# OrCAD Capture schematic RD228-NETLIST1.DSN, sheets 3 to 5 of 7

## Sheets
3 5: size A3
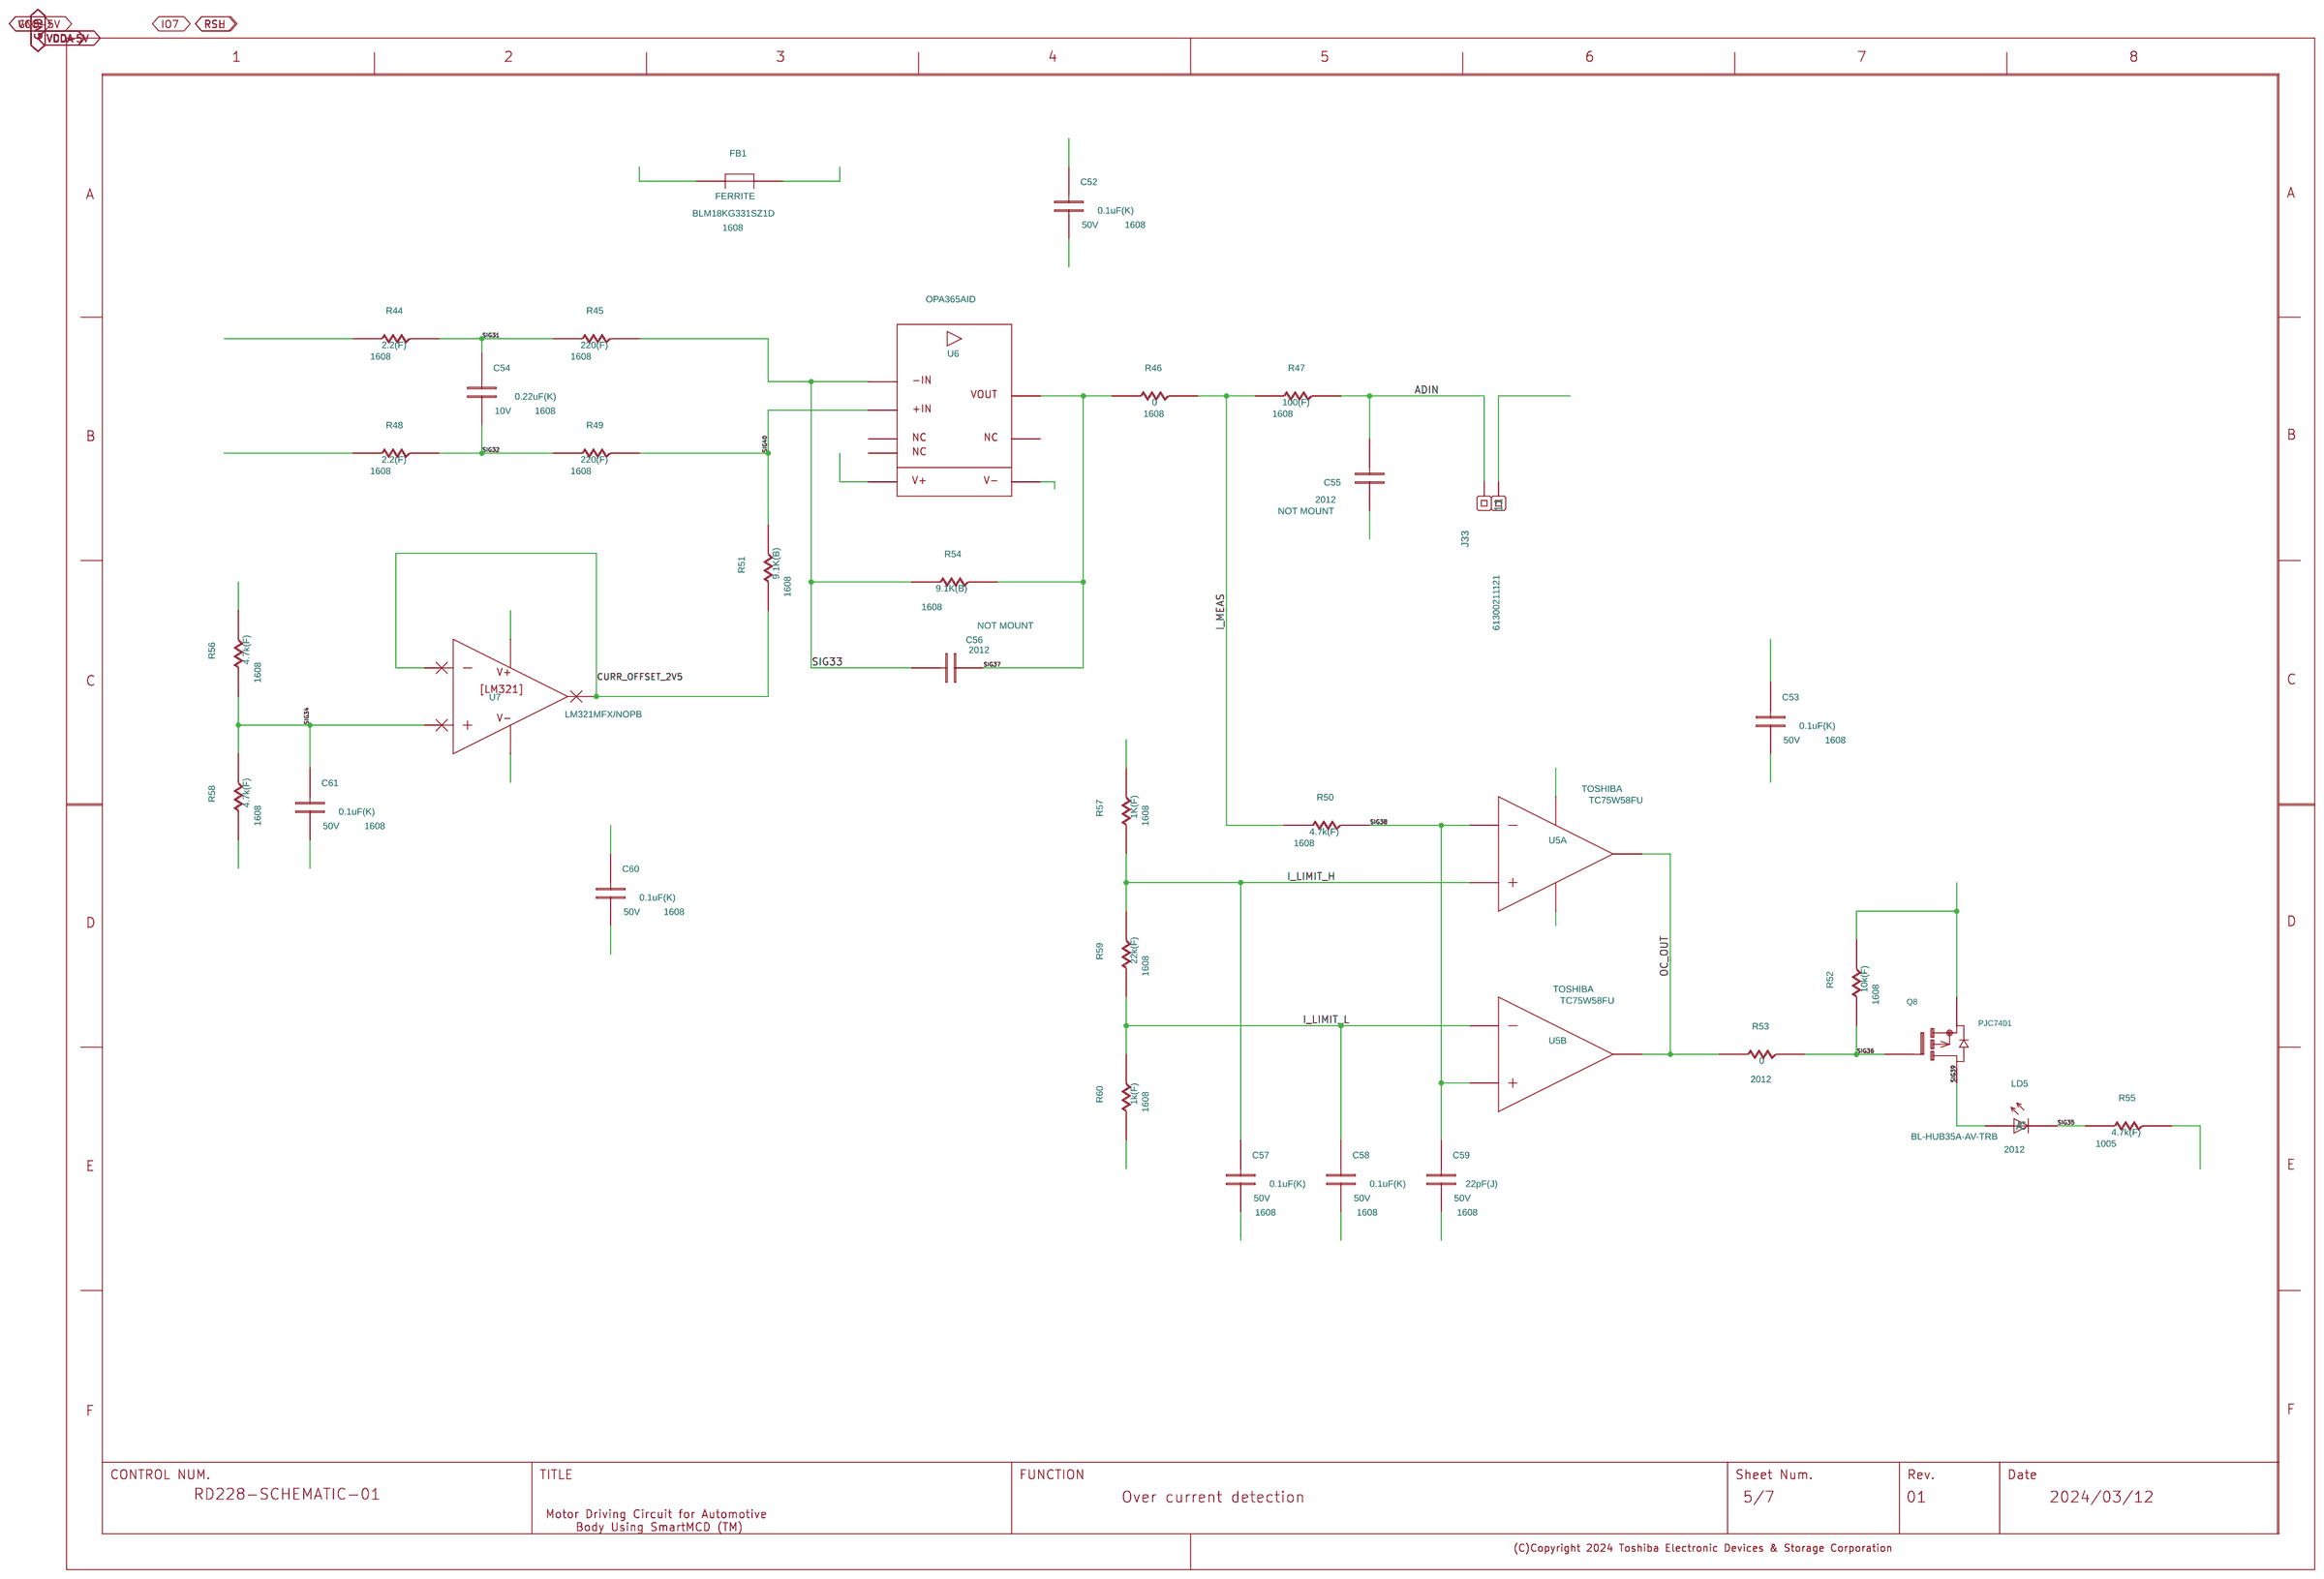
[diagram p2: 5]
4 4: size A3
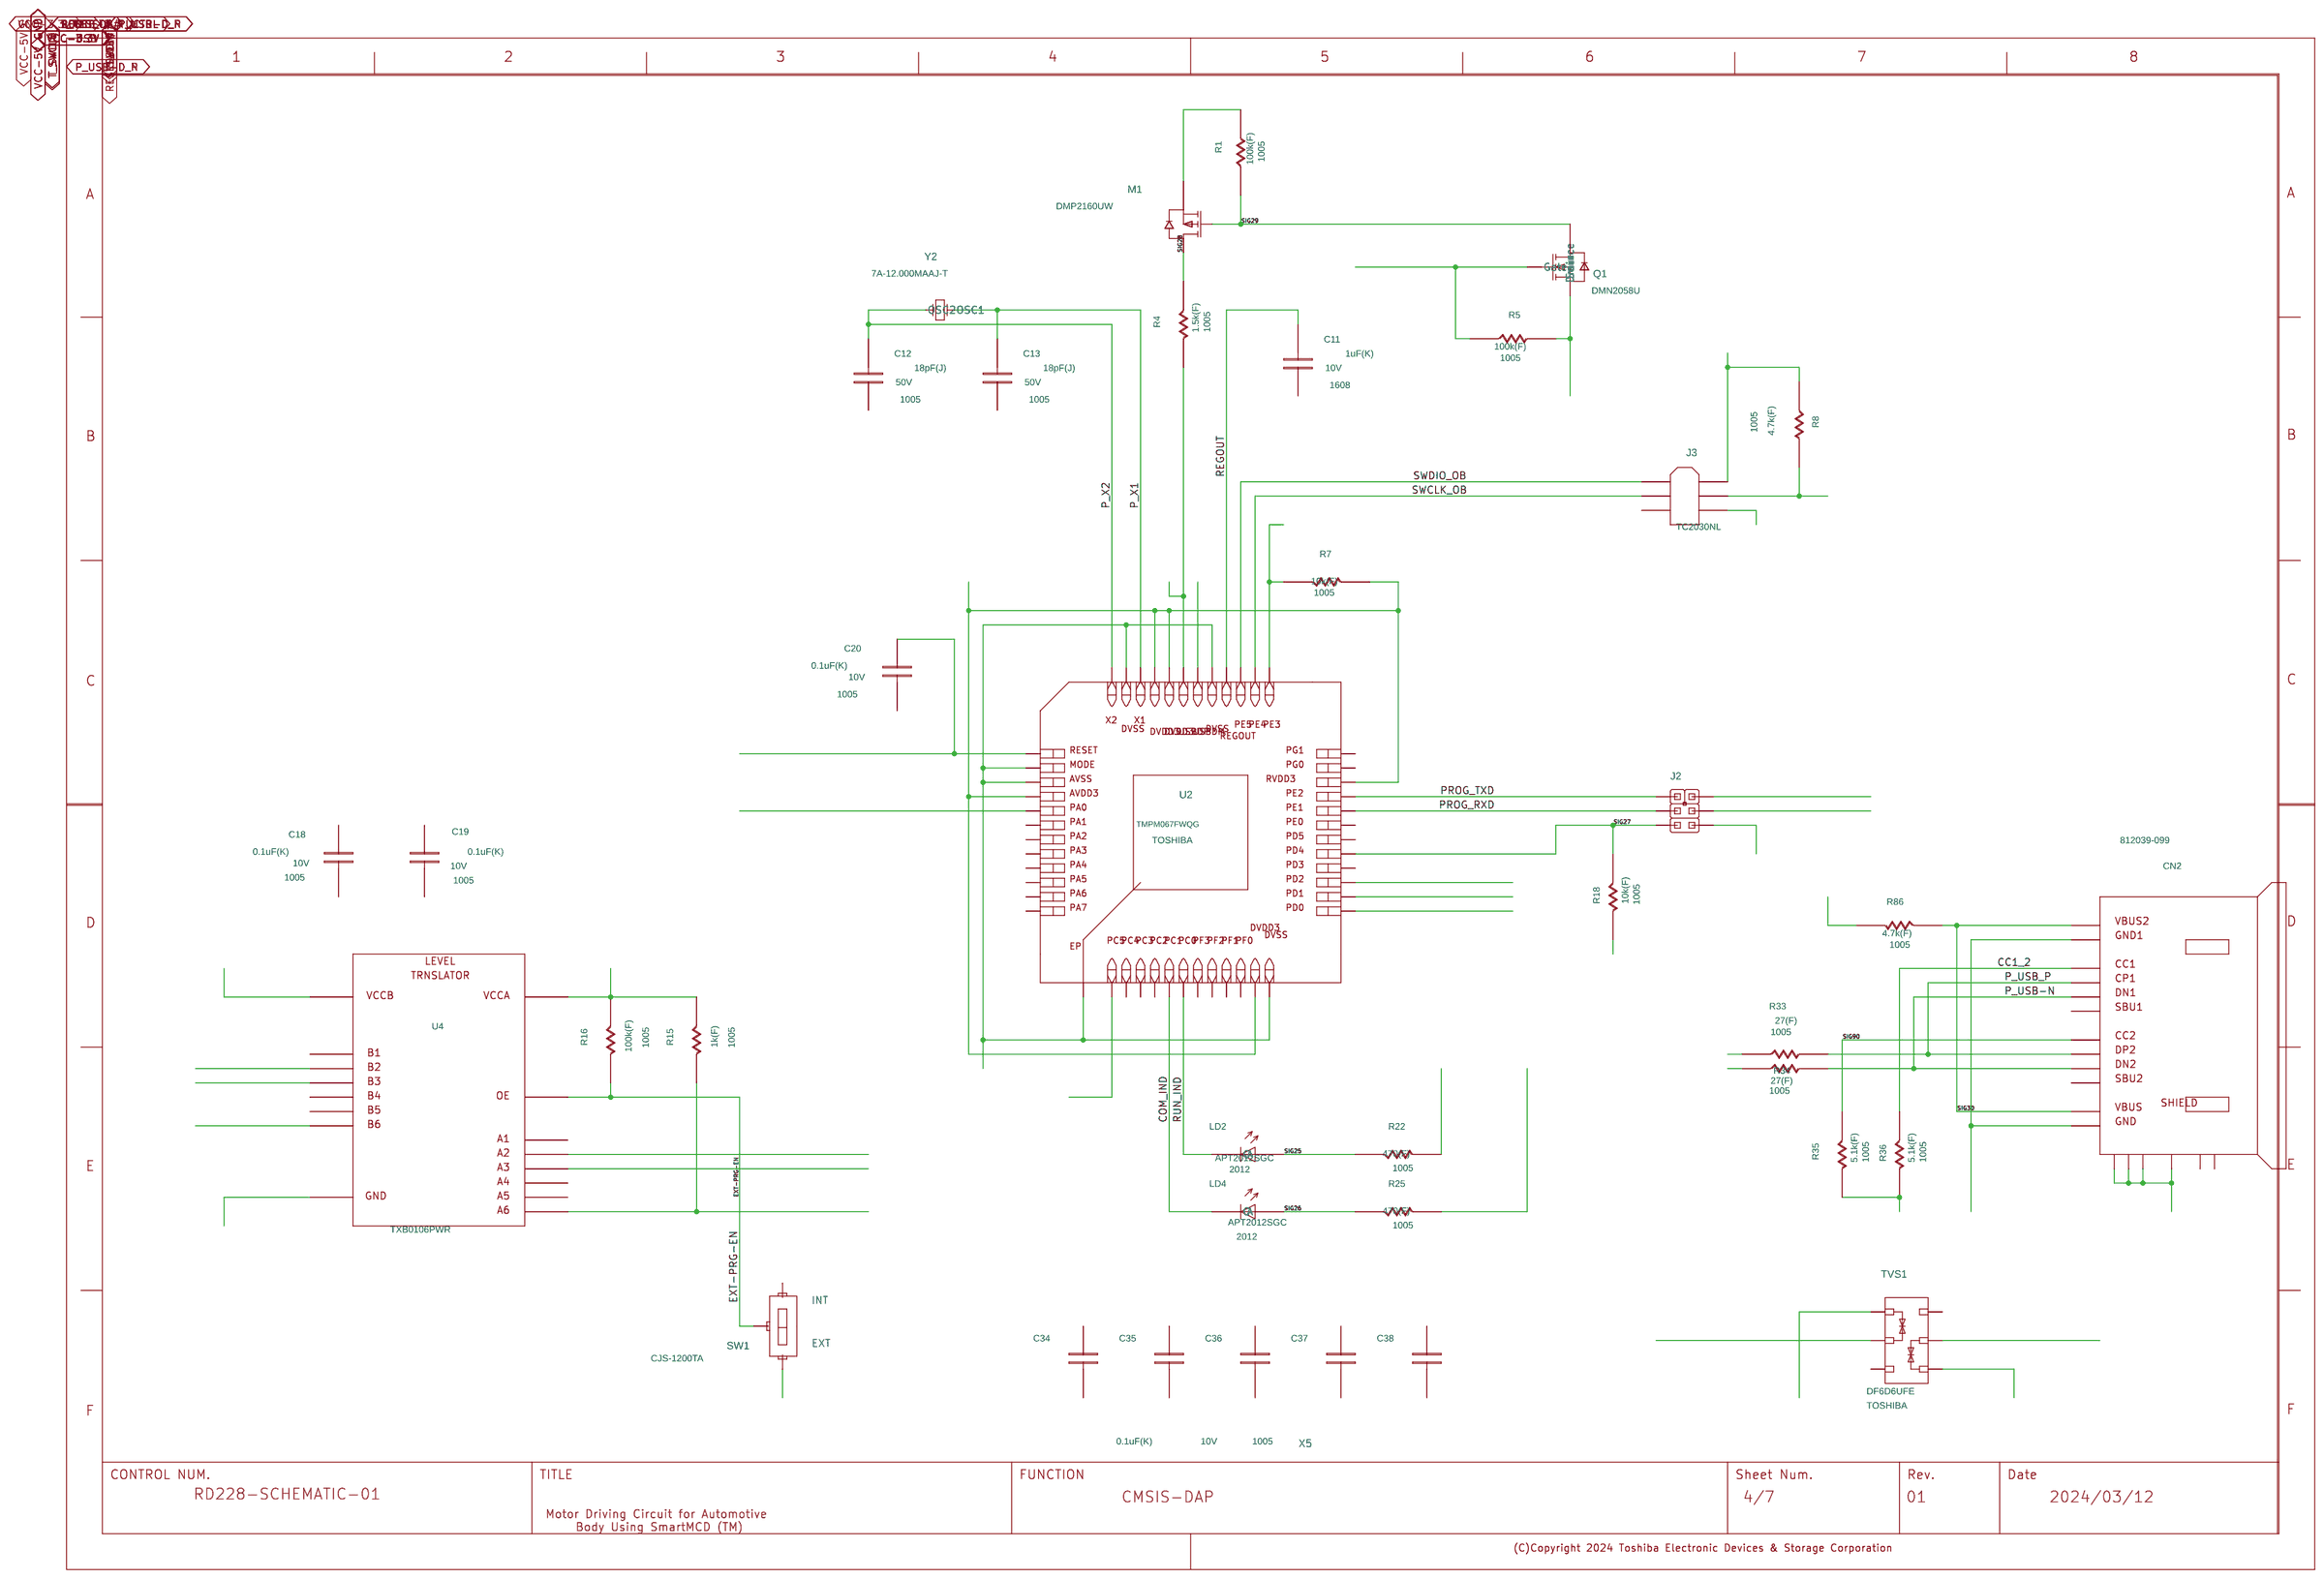
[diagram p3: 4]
5 3: size A3
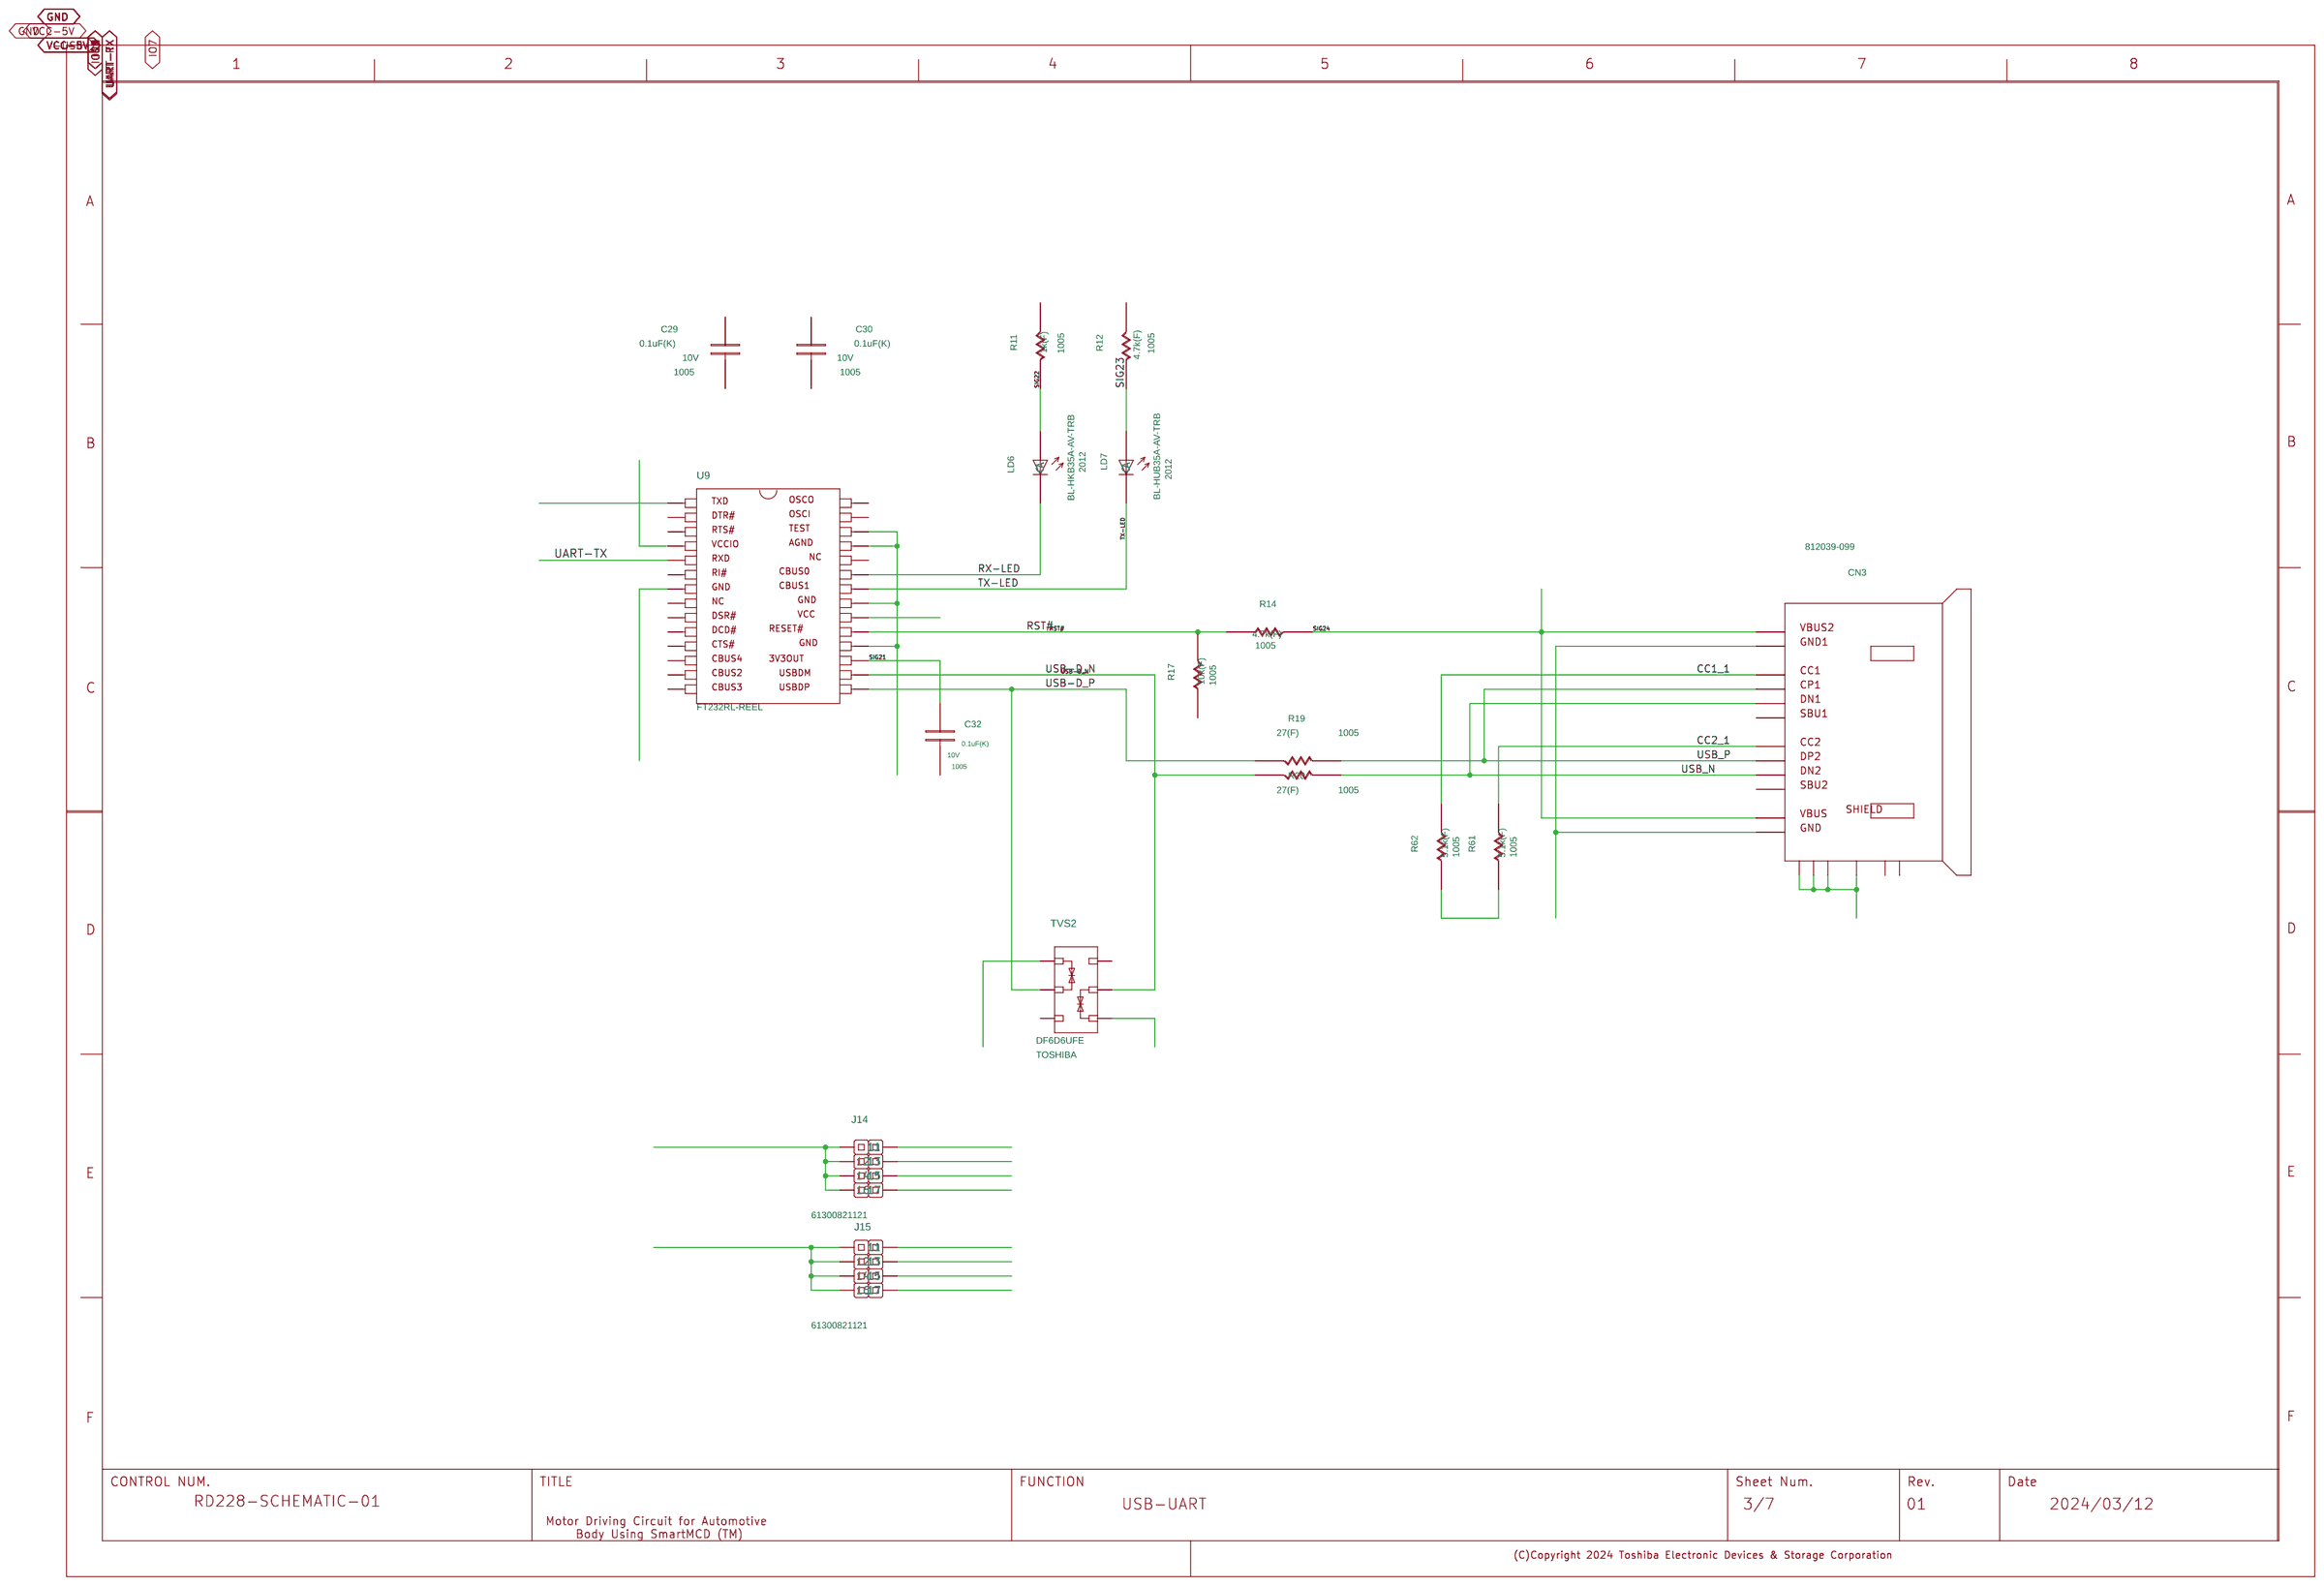
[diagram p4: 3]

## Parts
sheet 3
C29  C
C30  C
C32  C
CN3  USB-C
J14  HM 2x4
J15  HM 2x4
LD6  LED
LD7  LED
R11  R
R12  R
R14  R
R17  R
R19  R
R20  R
R61  R
R62  R
TVS2  NA
U9  FT232RL  [SSOP-28-NoOverlay]
U?#4  WAKU_DEF100
sheet 4
C11  0.1ƒÊF  [CAPC1005X55N-0402-NoOverlay]
C12  0.1ƒÊF  [CAPC1005X55N-0402-NoOverlay]
C13  0.1ƒÊF  [CAPC1005X55N-0402-NoOverlay]
C18  0.1ƒÊF  [CAPC1005X55N-0402-NoOverlay]
C19  0.1ƒÊF  [CAPC1005X55N-0402-NoOverlay]
C20  0.1ƒÊF  [CAPC1005X55N-0402-NoOverlay]
C34  0.1ƒÊF  [CAPC1005X55N-0402-NoOverlay]
C35  0.1ƒÊF  [CAPC1005X55N-0402-NoOverlay]
C36  0.1ƒÊF  [CAPC1005X55N-0402-NoOverlay]
C37  0.1ƒÊF  [CAPC1005X55N-0402-NoOverlay]
C38  0.1ƒÊF  [CAPC1005X55N-0402-NoOverlay]
CN2  USB-C
J2  M2X3
J3  CON-000241-01
LD2  LED
LD4  LED
M1  NA
Q1  MOSFET_N_CHQ1A
R1  R
R4  R
R5  R
R7  R
R8  R
R15  R
R16  R
R18  R
R22  R
R25  R
R33  R
R34  R
R35  R
R36  R
R86  R
SW1  NA
TVS1  NA
U2  NA
U4  TXB0106
U?#3  WAKU_DEF100
Y2  12MHz
sheet 5
C52  0.10ƒÊF  [CAPC1608X55N-0603-NoOverlay]
C53  0.10ƒÊF  [CAPC1608X55N-0603-NoOverlay]
C54  0.22ƒÊF  [CAPC1608X55N-0603-NoOverlay]
C55  NF  [CAPC2013X100N-0805-NoOverlay]
C56  NF  [CAPC2013X100N-0805-NoOverlay]
C57  0.10ƒÊF  [CAPC1608X55N-0603-NoOverlay]
C58  0.10ƒÊF  [CAPC1608X55N-0603-NoOverlay]
C59  22pF  [CAPC1608X55N-0603-NoOverlay]
C60  0.10ƒÊF  [CAPC1608X55N-0603-NoOverlay]
C61  0.10ƒÊF  [CAPC1608X55N-0603-NoOverlay]
FB1  FERRITE  [INDC1608X95N-0603-NOOVERLAY]
J33  M1X2
LD5  FLT1  [DIOREDC2013X120N-0805-NoOverlay]
Q8  NA  [SOT65P210X100-3N-NoOverlay]
R44  2.2R  [RESC1508X55N-0603-NOOVERLAY]
R45  220  [RESC1508X55N-0603-NOOVERLAY]
R46  0R  [RESC1508X55N-0603-NOOVERLAY]
R47  100  [RESC1508X55N-0603-NOOVERLAY]
R48  2.2R  [RESC1508X55N-0603-NOOVERLAY]
R49  220  [RESC1508X55N-0603-NOOVERLAY]
R50  4.7k  [RESC1508X55N-0603-NOOVERLAY]
R51  9.1k  [RESC1508X55N-0603-NOOVERLAY]
R52  10k  [RESC1508X55N-0603-NOOVERLAY]
R53  0.0  [RESC2013X38N-0805-NOOVERLAY]
R54  9.1k  [RESC1508X55N-0603-NOOVERLAY]
R55  4.7k  [RESC1005X40N-0402-NOOVERLAY]
R56  4.7k  [RESC1508X55N-0603-NOOVERLAY]
R57  1k  [RESC1508X55N-0603-NOOVERLAY]
R58  4.7k  [RESC1508X55N-0603-NOOVERLAY]
R59  22k  [RESC1508X55N-0603-NOOVERLAY]
R60  1k  [RESC1508X55N-0603-NOOVERLAY]
U5  NA  [SOP65P400X110-8L30N-TSSOP-8-NoOverlay]  (sections A,B)
U6  NA  [SOIC8P127_490X600X175L83X41N-SOIC8_-_NoOverlay]
U7  NA  [SOT95P280X145-5L30N-SOT23-5-NoOverlay]
U?#2  WAKU_DEF100

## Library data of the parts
C29 C30 C32 = C: COMPONENTTYPE: 4; SAVECOUNT: 0; SIZECODESMD: 1005; VAL1: 0.1uF(K); VAL2: 10V
CN2 CN3 = USB-C: COMP: USB_TYPE_C_CN2; COMPONENTTYPE: 4; VAL3: 812039-099
J14 = HM_2X4_J14: COMPONENTTYPE: 4; LAYOUTNAME: Z-7dc569f5-73f0-43d2-99fa-c8247dcaffbd.cmp50; VAL3: 61300821121
J15 = HM_2X4_J14: COMPONENTTYPE: 4; LAYOUTNAME: Z-7dc569f5-73f0-43d2-99fa-c8247dcaffbd.cmp54; VAL3: 61300821121
LD6 = LED: COMPONENTTYPE: 4; LAYOUTNAME: Z-7dc569f5-73f0-43d2-99fa-c8247dcaffbd.cmp70; SIZECODESMD: 2012; UPDATEDATE: 06/10/13; UPDATETIME: 13:54:07; UPDATEUSER: fukuda-y; VAL1: YELLOW; VAL3: BL-HKB35A-AV-TRB
LD7 = LED: COMPONENTTYPE: 4; LAYOUTNAME: Z-7dc569f5-73f0-43d2-99fa-c8247dcaffbd.cmp71; SIZECODESMD: 2012; UPDATEDATE: 06/10/13; UPDATETIME: 13:54:07; UPDATEUSER: fukuda-y; VAL1: RED; VAL3: BL-HUB35A-AV-TRB
R11 R15 = R: COMPONENTTYPE: 4; SAVECOUNT: 0; SIZECODESMD: 1005; VAL1: 1k(F); VAL2: 63mW
R8 R12 R86 = R: COMPONENTTYPE: 4; SAVECOUNT: 0; SIZECODESMD: 1005; VAL1: 4.7k(F); VAL2: 63mW
R14 = R: COMPONENTTYPE: 4; LAYOUTNAME: Z-7dc569f5-73f0-43d2-99fa-c8247dcaffbd.cmp79; SAVECOUNT: 0; SIZECODESMD: 1005; VAL1: 4.7k(F); VAL2: 63mW
R7 R17 R18 = R: COMPONENTTYPE: 4; SAVECOUNT: 0; SIZECODESMD: 1005; VAL1: 10k(F); VAL2: 63mW
R19 R20 = R: COMPONENTTYPE: 4; SAVECOUNT: 0; SIZECODESMD: 1005; VAL1: 27(F); VAL2: 63mW
R35 R36 R61 R62 = R: COMPONENTTYPE: 4; SAVECOUNT: 0; SIZECODESMD: 1005; VAL1: 5.1k(F); VAL2: 63mW
TVS2 = DF6D6UFE_L3F_TVS1: COMPONENTTYPE: 4; LAYOUTNAME: Z-7dc569f5-73f0-43d2-99fa-c8247dcaffbd.cmp105; USERCOMPTEXT3: TOSHIBA; VAL3: DF6D6UFE
U9 = FT232RL_U9: COMPONENTNAME: FT232RL_U9_FT232RL_U9; COMPONENTTYPE: 4; INSTANCENAME: INS4949; LAYOUTNAME: Z-7dc569f5-73f0-43d2-99fa-c8247dcaffbd.cmp9; UPDATEDATE: 2024/2/16; UPDATETIME: 16:56:39; VAL3: FT232RL-REEL
U?#4 = WAKU_DEF100: AUTHOR: w20165dm; COMPONENTTYPE: 2; DATE: 2024/03/12; DRAWINGNUMBER: RD228-SCHEMATIC-01; FUNCTION: USB-UART; LAYOUTNAME: Z-7dc569f5-73f0-43d2-99fa-c8247dcaffbd.cmp39; REVISION: 01; SAVEAREA0: 185750,-43960,448537,75779; SAVECOUNT: 9; SHEETNUMBER: 3/7; SHTSAVECOUNT: 40; TIME: 13:11:45; TITLE: Motor Driving Circuit for Automotive / Body Using SmartMCD (TM); UPDATEDATE: 2024/03/26; UPDATETIME: 12:23:37
C11 = C: ASSEMBLY: SMD; AUTHOR: t5459927; BARCODE: 2911010025755; CATEGORY: Capacitors; COMP: Capacitor_Ceramic_C19; COMPONENTTYPE: 4; DATASHEET URL: http://ds.yuden.co.jp/TYCOMPAS/ut/detail.do?productNo; DATE: 2024/2/16; FAMILY: CERAMIC CAPACITOR; INSTANCENAME: INS3745; LAYOUTNAME: Z-3a01232a-ff64-4668-b530-789526b9f0c3.cmp194; MANUFACTURER: Taiyo Yuden; MANUFACTURER PART NUMBER: LMK105BJ104KV-F; NUMBER DEVICES IN PACKAGE: 1; PACKAGE CASE: 0402 (1005 Metric); PART TYPE: Capacitors; PIN NAMES ROTATE: True; PIN NAMES VISIBLE: False; PIN NUMBERS VISIBLE: False; RECOMMENDED RATING: Platinum; SAVECOUNT: 0; SIZECODESMD: 1608; TEMPERATURE COEFFICIENT: X5R; TIME: 16:56:44; TOLERANCE: }10%; UPDATEDATE: 2024/2/16; UPDATETIME: 16:56:44; UPDATEUSER: t5459927; VAL1: 1uF(K); VAL2: 10V; VOLTAGE RATED: 10V
C12 = C: ASSEMBLY: SMD; AUTHOR: t5459927; BARCODE: 2911010025755; CATEGORY: Capacitors; COMP: Capacitor_Ceramic_C19; COMPONENTTYPE: 4; DATASHEET URL: http://ds.yuden.co.jp/TYCOMPAS/ut/detail.do?productNo; DATE: 2024/2/16; FAMILY: CERAMIC CAPACITOR; INSTANCENAME: INS3745; LAYOUTNAME: Z-3a01232a-ff64-4668-b530-789526b9f0c3.cmp185; MANUFACTURER: Taiyo Yuden; MANUFACTURER PART NUMBER: LMK105BJ104KV-F; NUMBER DEVICES IN PACKAGE: 1; PACKAGE CASE: 0402 (1005 Metric); PART TYPE: Capacitors; PIN NAMES ROTATE: True; PIN NAMES VISIBLE: False; PIN NUMBERS VISIBLE: False; RECOMMENDED RATING: Platinum; SAVECOUNT: 0; SIZECODESMD: 1005; TEMPERATURE COEFFICIENT: X5R; TIME: 16:56:44; TOLERANCE: }10%; UPDATEDATE: 2024/2/16; UPDATETIME: 16:56:44; UPDATEUSER: t5459927; VAL1: 18pF(J); VAL2: 50V; VOLTAGE RATED: 10V
C13 = C: ASSEMBLY: SMD; AUTHOR: t5459927; BARCODE: 2911010025755; CATEGORY: Capacitors; COMP: Capacitor_Ceramic_C19; COMPONENTTYPE: 4; DATASHEET URL: http://ds.yuden.co.jp/TYCOMPAS/ut/detail.do?productNo; DATE: 2024/2/16; FAMILY: CERAMIC CAPACITOR; INSTANCENAME: INS3745; LAYOUTNAME: Z-3a01232a-ff64-4668-b530-789526b9f0c3.cmp189; MANUFACTURER: Taiyo Yuden; MANUFACTURER PART NUMBER: LMK105BJ104KV-F; NUMBER DEVICES IN PACKAGE: 1; PACKAGE CASE: 0402 (1005 Metric); PART TYPE: Capacitors; PIN NAMES ROTATE: True; PIN NAMES VISIBLE: False; PIN NUMBERS VISIBLE: False; RECOMMENDED RATING: Platinum; SAVECOUNT: 0; SIZECODESMD: 1005; TEMPERATURE COEFFICIENT: X5R; TIME: 16:56:44; TOLERANCE: }10%; UPDATEDATE: 2024/2/16; UPDATETIME: 16:56:44; UPDATEUSER: t5459927; VAL1: 18pF(J); VAL2: 50V; VOLTAGE RATED: 10V
C18 = C: ASSEMBLY: SMD; AUTHOR: t5459927; BARCODE: 2911010025755; CATEGORY: Capacitors; COMP: Capacitor_Ceramic_C18; COMPONENTTYPE: 4; DATASHEET URL: http://ds.yuden.co.jp/TYCOMPAS/ut/detail.do?productNo; DATE: 2024/2/16; FAMILY: CERAMIC CAPACITOR; INSTANCENAME: INS3745; MANUFACTURER: Taiyo Yuden; MANUFACTURER PART NUMBER: LMK105BJ104KV-F; NUMBER DEVICES IN PACKAGE: 1; PACKAGE CASE: 0402 (1005 Metric); PART TYPE: Capacitors; PIN NAMES ROTATE: True; PIN NAMES VISIBLE: False; PIN NUMBERS VISIBLE: False; RECOMMENDED RATING: Platinum; SAVECOUNT: 0; SIZECODESMD: 1005; TEMPERATURE COEFFICIENT: X5R; TIME: 16:56:44; TOLERANCE: }10%; UPDATEDATE: 2024/2/16; UPDATETIME: 16:56:44; UPDATEUSER: t5459927; VAL1: 0.1uF(K); VAL2: 10V; VOLTAGE RATED: 10V
C19 C34-C38 = C: ASSEMBLY: SMD; AUTHOR: t5459927; BARCODE: 2911010025755; CATEGORY: Capacitors; COMP: Capacitor_Ceramic_C19; COMPONENTTYPE: 4; DATASHEET URL: http://ds.yuden.co.jp/TYCOMPAS/ut/detail.do?productNo; DATE: 2024/2/16; FAMILY: CERAMIC CAPACITOR; INSTANCENAME: INS3745; MANUFACTURER: Taiyo Yuden; MANUFACTURER PART NUMBER: LMK105BJ104KV-F; NUMBER DEVICES IN PACKAGE: 1; PACKAGE CASE: 0402 (1005 Metric); PART TYPE: Capacitors; PIN NAMES ROTATE: True; PIN NAMES VISIBLE: False; PIN NUMBERS VISIBLE: False; RECOMMENDED RATING: Platinum; SAVECOUNT: 0; SIZECODESMD: 1005; TEMPERATURE COEFFICIENT: X5R; TIME: 16:56:44; TOLERANCE: }10%; UPDATEDATE: 2024/2/16; UPDATETIME: 16:56:44; UPDATEUSER: t5459927; VAL1: 0.1uF(K); VAL2: 10V; VOLTAGE RATED: 10V
C20 = C: ASSEMBLY: SMD; AUTHOR: t5459927; BARCODE: 2911010025755; CATEGORY: Capacitors; COMP: Capacitor_Ceramic_C20; COMPONENTTYPE: 4; DATASHEET URL: http://ds.yuden.co.jp/TYCOMPAS/ut/detail.do?productNo; DATE: 2024/2/16; FAMILY: CERAMIC CAPACITOR; INSTANCENAME: INS3745; MANUFACTURER: Taiyo Yuden; MANUFACTURER PART NUMBER: LMK105BJ104KV-F; NUMBER DEVICES IN PACKAGE: 1; PACKAGE CASE: 0402 (1005 Metric); PART TYPE: Capacitors; PIN NAMES ROTATE: True; PIN NAMES VISIBLE: False; PIN NUMBERS VISIBLE: False; RECOMMENDED RATING: Platinum; SAVECOUNT: 0; SIZECODESMD: 1005; TEMPERATURE COEFFICIENT: X5R; TIME: 16:56:44; TOLERANCE: }10%; UPDATEDATE: 2024/2/16; UPDATETIME: 16:56:44; UPDATEUSER: t5459927; VAL1: 0.1uF(K); VAL2: 10V; VOLTAGE RATED: 10V
J2 = JUMPER3_ALT_J2: COMPONENTTYPE: 4; LAYOUTNAME: Z-3a01232a-ff64-4668-b530-789526b9f0c3.cmp174; VAL3: 892-70-006-10-001101
J3 = CON_000241_01_J3: COMPONENTTYPE: 4; LAYOUTNAME: Z-3a01232a-ff64-4668-b530-789526b9f0c3.cmp232; VAL3: TC2030NL
LD2 = LED: COMP: APT2012SGC; COMPONENTTYPE: 4; LAYOUTNAME: Z-3a01232a-ff64-4668-b530-789526b9f0c3.cmp168; SIZECODESMD: 2012; UPDATEDATE: 06/10/13; UPDATETIME: 13:54:07; UPDATEUSER: fukuda-y; VAL1: GREEN; VAL3: APT2012SGC
LD4 = LED: COMP: APT2012SGC; COMPONENTTYPE: 4; LAYOUTNAME: Z-3a01232a-ff64-4668-b530-789526b9f0c3.cmp169; SIZECODESMD: 2012; UPDATEDATE: 06/10/13; UPDATETIME: 13:54:07; UPDATEUSER: fukuda-y; VAL1: GREEN; VAL3: APT2012SGC
M1 = MOSFET_P_CH_M1: COMPONENTTYPE: 4; LAYOUTNAME: Z-3a01232a-ff64-4668-b530-789526b9f0c3.cmp191; VAL3: DMP2160UW
Q1 = MOSFET_N_CHQ1A: COMP: Q; COMPONENTKIND: 0; COMPONENTTYPE: 4; LAYOUTNAME: Z-3a01232a-ff64-4668-b530-789526b9f0c3.cmp228; VAL3: DMN2058U
R1 = R: COMPONENTTYPE: 4; LAYOUTNAME: Z-3a01232a-ff64-4668-b530-789526b9f0c3.cmp195; SAVECOUNT: 0; SIZECODESMD: 1005; VAL1: 100k(F); VAL2: 100mW
R4 = R: COMPONENTTYPE: 4; SAVECOUNT: 0; SIZECODESMD: 1005; VAL1: 1.5k(F); VAL2: 100mW
R5 = R: COMPONENTTYPE: 4; LAYOUTNAME: Z-3a01232a-ff64-4668-b530-789526b9f0c3.cmp199; SAVECOUNT: 0; SIZECODESMD: 1005; VAL1: 100k(F); VAL2: 100mW
R16 = R: COMPONENTTYPE: 4; SAVECOUNT: 0; SIZECODESMD: 1005; VAL1: 100k(F); VAL2: 63mW
R22 R25 = R: COMPONENTTYPE: 4; SAVECOUNT: 0; SIZECODESMD: 1005; VAL1: 470(F); VAL2: 63mW
R33 = R: COMPONENTTYPE: 4; LAYOUTNAME: Z-3a01232a-ff64-4668-b530-789526b9f0c3.cmp215; SAVECOUNT: 0; SIZECODESMD: 1005; VAL1: 27(F); VAL2: 63mW
R34 = R: COMPONENTTYPE: 4; LAYOUTNAME: Z-3a01232a-ff64-4668-b530-789526b9f0c3.cmp216; SAVECOUNT: 0; SIZECODESMD: 1005; VAL1: 27(F); VAL2: 63mW
SW1 = CAS_120TA_SW1: COMPONENTTYPE: 4; LAYOUTNAME: Z-3a01232a-ff64-4668-b530-789526b9f0c3.cmp84; VAL3: CJS-1200TA
TVS1 = DF6D6UFE_L3F_TVS1: COMPONENTTYPE: 4; LAYOUTNAME: Z-3a01232a-ff64-4668-b530-789526b9f0c3.cmp222; USERCOMPTEXT3: TOSHIBA; VAL3: DF6D6UFE
U2 = TMPM067FWQG_U2: COMPONENTTYPE: 4; LAYOUTNAME: Z-3a01232a-ff64-4668-b530-789526b9f0c3.cmp229; USERCOMPTEXT3: TOSHIBA; VAL3: TMPM067FWQG
U4 = TXB0106: COMP: U; COMPONENTTYPE: 4; LAYOUTNAME: Z-3a01232a-ff64-4668-b530-789526b9f0c3.cmp93; VAL3: TXB0106PWR
U?#3 = WAKU_DEF100: AUTHOR: w20165dm; COMPONENTTYPE: 2; DATE: 2024/03/12; DRAWINGNUMBER: RD228-SCHEMATIC-01; FUNCTION: CMSIS-DAP; LAYOUTNAME: Z-3a01232a-ff64-4668-b530-789526b9f0c3.cmp82; REVISION: 01; SAVEAREA0: 185750,-43960,448537,75779; SAVECOUNT: 9; SHEETNUMBER: 4/7; SHTSAVECOUNT: 62; TIME: 13:11:54; TITLE: Motor Driving Circuit for Automotive / Body Using SmartMCD (TM); UPDATEDATE: 2024/03/18; UPDATETIME: 20:08:52
Y2 = CRYSTAL_Y2: COMPONENTTYPE: 4; LAYOUTNAME: Z-3a01232a-ff64-4668-b530-789526b9f0c3.cmp188; VAL3: 7A-12.000MAAJ-T
C52 = C: ASSEMBLY: SMD; AUTHOR: t5459927; BARCODE: 0100000012857; CATEGORY: Capacitors; COMP: Capacitor_Ceramic_C52; COMPONENTNAME: Capacitor_Ceramic_C52_Capacitor_Ceramic_C52; COMPONENTTYPE: 4; DATASHEET URL: http://www.samsungsem.com/kr/support/product-search/mlcc/CL10B104KB8NNNC.jsp; DATE: 2024/2/16; FAMILY: CERAMIC CAPACITOR; ID: 275; INSTANCENAME: INS4165; ITEM_ID: 1703; LAYOUTNAME: Z-99fa7a59-0340-4c54-926f-366210f15152.cmp12; MANUFACTURER: Samsung Electro-Mechanics America, Inc.; MANUFACTURER PART NUMBER: CL10B104KB8NNNC; NUMBER DEVICES IN PACKAGE: 1; PACKAGE CASE: 0603 (1608 Metric); PART TYPE: Capacitors; PIN NAMES ROTATE: True; PIN NAMES VISIBLE: False; PIN NUMBERS VISIBLE: False; SAVECOUNT: 0; SIZECODESMD: 1608; TEMPERATURE COEFFICIENT: X7R; TIME: 16:56:37; TOLERANCE: }10%; UPDATEDATE: 2024/2/16; UPDATETIME: 16:56:37; UPDATEUSER: t5459927; VAL1: 0.1uF(K); VAL2: 50V; VAL3: CL10B104KB8NNNC; VOLTAGE RATED: 50V
C53 = C: ASSEMBLY: SMD; AUTHOR: t5459927; BARCODE: 0100000012857; CATEGORY: Capacitors; COMP: Capacitor_Ceramic_C53; COMPONENTNAME: Capacitor_Ceramic_C53_Capacitor_Ceramic_C53; COMPONENTTYPE: 4; DATASHEET URL: http://www.samsungsem.com/kr/support/product-search/mlcc/CL10B104KB8NNNC.jsp; DATE: 2024/2/16; FAMILY: CERAMIC CAPACITOR; ID: 275; INSTANCENAME: INS4313; ITEM_ID: 1703; LAYOUTNAME: Z-99fa7a59-0340-4c54-926f-366210f15152.cmp15; MANUFACTURER: Samsung Electro-Mechanics America, Inc.; MANUFACTURER PART NUMBER: CL10B104KB8NNNC; NUMBER DEVICES IN PACKAGE: 1; PACKAGE CASE: 0603 (1608 Metric); PART TYPE: Capacitors; PIN NAMES ROTATE: True; PIN NAMES VISIBLE: False; PIN NUMBERS VISIBLE: False; SAVECOUNT: 0; SIZECODESMD: 1608; TEMPERATURE COEFFICIENT: X7R; TIME: 16:56:55; TOLERANCE: }10%; UPDATEDATE: 2024/2/16; UPDATETIME: 16:56:55; UPDATEUSER: t5459927; VAL1: 0.1uF(K); VAL2: 50V; VAL3: CL10B104KB8NNNC; VOLTAGE RATED: 50V
C54 = C: ASSEMBLY: SMD; AUTHOR: t5459927; BARCODE: 3500000320896; CATEGORY: Capacitors; COMP: Capacitor_Ceramic_C54; COMPONENTNAME: Capacitor_Ceramic_C54_Capacitor_Ceramic_C54; COMPONENTTYPE: 4; DATASHEET URL: http://www.calchipelectronics.com/pdf/gmc_series.pdf; DATE: 2024/2/16; FAMILY: CERAMIC CAPACITOR; ID: 1358; INSTANCENAME: INS4245; ITEM_ID: 29240; LAYOUTNAME: Z-99fa7a59-0340-4c54-926f-366210f15152.cmp33; MANUFACTURER: CAL-CHIP ELECTRONICS, INC.; MANUFACTURER PART NUMBER: GMC10X7R224K10NT; NUMBER DEVICES IN PACKAGE: 1; PACKAGE CASE: 0603 (1608 Metric); PART TYPE: Capacitors; PIN NAMES ROTATE: True; PIN NAMES VISIBLE: False; PIN NUMBERS VISIBLE: False; SAVECOUNT: 0; SIZECODESMD: 1608; TEMPERATURE COEFFICIENT: X7R; TIME: 16:56:54; TOLERANCE: }10%; UPDATEDATE: 2024/2/16; UPDATETIME: 16:56:54; UPDATEUSER: t5459927; VAL1: 0.22uF(K); VAL2: 10V; VAL3: GMC10X7R224K10NT; VOLTAGE RATED: 10V
C55 = C: ASSEMBLY: SMD; AUTHOR: t5459927; BARCODE: 0100000001868; CAPACITANCE: 100n; CATEGORY: Capacitors; COMP: Capacitor_Ceramic_C55; COMPONENTNAME: Capacitor_Ceramic_C55_Capacitor_Ceramic_C55; COMPONENTTYPE: 4; DATE: 2024/2/16; FAMILY: CERAMIC CAPACITOR; ID: 136; INSTANCENAME: INS4255; ITEM_ID: 450; LAYOUTNAME: Z-99fa7a59-0340-4c54-926f-366210f15152.cmp55; MANUFACTURER: Yageo; MANUFACTURER PART NUMBER: CC0805KRX7R9BB104; NOTMOUNT: NOT MOUNT; NUMBER DEVICES IN PACKAGE: 1; PACKAGE CASE: 0805; PART TYPE: Capacitors; PIN NAMES ROTATE: True; PIN NAMES VISIBLE: False; PIN NUMBERS VISIBLE: False; RECOMMENDED RATING: Platinum; SAVECOUNT: 0; TEMPERATURE COEFFICIENT: X7R; TIME: 16:56:44; TOLERANCE: 10%; UPDATEDATE: 2024/2/16; UPDATETIME: 16:56:44; UPDATEUSER: t5459927; VAL3: 2012; VOLTAGE RATED: 50
C56 = C: ASSEMBLY: SMD; AUTHOR: t5459927; BARCODE: 0100000001868; CAPACITANCE: 100n; CATEGORY: Capacitors; COMP: Capacitor_Ceramic_C56; COMPONENTNAME: Capacitor_Ceramic_C56_Capacitor_Ceramic_C56; COMPONENTTYPE: 4; DATE: 2024/2/16; FAMILY: CERAMIC CAPACITOR; ID: 136; INSTANCENAME: INS4265; ITEM_ID: 450; LAYOUTNAME: Z-99fa7a59-0340-4c54-926f-366210f15152.cmp8; MANUFACTURER: Yageo; MANUFACTURER PART NUMBER: CC0805KRX7R9BB104; NOTMOUNT: NOT MOUNT; NUMBER DEVICES IN PACKAGE: 1; PACKAGE CASE: 0805; PART TYPE: Capacitors; PIN NAMES ROTATE: True; PIN NAMES VISIBLE: False; PIN NUMBERS VISIBLE: False; RECOMMENDED RATING: Platinum; SAVECOUNT: 0; TEMPERATURE COEFFICIENT: X7R; TIME: 16:56:58; TOLERANCE: 10%; UPDATEDATE: 2024/2/16; UPDATETIME: 16:56:58; UPDATEUSER: t5459927; VAL3: 2012; VOLTAGE RATED: 50
C57 = C: ASSEMBLY: SMD; AUTHOR: t5459927; BARCODE: 0100000012857; CATEGORY: Capacitors; COMP: Capacitor_Ceramic_C57; COMPONENTNAME: Capacitor_Ceramic_C57_Capacitor_Ceramic_C57; COMPONENTTYPE: 4; DATASHEET URL: http://www.samsungsem.com/kr/support/product-search/mlcc/CL10B104KB8NNNC.jsp; DATE: 2024/2/16; FAMILY: CERAMIC CAPACITOR; ID: 275; INSTANCENAME: INS4343; ITEM_ID: 1703; LAYOUTNAME: Z-99fa7a59-0340-4c54-926f-366210f15152.cmp54; MANUFACTURER: Samsung Electro-Mechanics America, Inc.; MANUFACTURER PART NUMBER: CL10B104KB8NNNC; NUMBER DEVICES IN PACKAGE: 1; PACKAGE CASE: 0603 (1608 Metric); PART TYPE: Capacitors; PIN NAMES ROTATE: True; PIN NAMES VISIBLE: False; PIN NUMBERS VISIBLE: False; SAVECOUNT: 0; SIZECODESMD: 1608; TEMPERATURE COEFFICIENT: X7R; TIME: 16:56:48; TOLERANCE: }10%; UPDATEDATE: 2024/2/16; UPDATETIME: 16:56:48; UPDATEUSER: t5459927; VAL1: 0.1uF(K); VAL2: 50V; VAL3: CL10B104KB8NNNC; VOLTAGE RATED: 50V
C58 = C: ASSEMBLY: SMD; AUTHOR: t5459927; BARCODE: 0100000012857; CATEGORY: Capacitors; COMP: Capacitor_Ceramic_C58; COMPONENTNAME: Capacitor_Ceramic_C58_Capacitor_Ceramic_C58; COMPONENTTYPE: 4; DATASHEET URL: http://www.samsungsem.com/kr/support/product-search/mlcc/CL10B104KB8NNNC.jsp; DATE: 2024/2/16; FAMILY: CERAMIC CAPACITOR; ID: 275; INSTANCENAME: INS4333; ITEM_ID: 1703; LAYOUTNAME: Z-99fa7a59-0340-4c54-926f-366210f15152.cmp6; MANUFACTURER: Samsung Electro-Mechanics America, Inc.; MANUFACTURER PART NUMBER: CL10B104KB8NNNC; NUMBER DEVICES IN PACKAGE: 1; PACKAGE CASE: 0603 (1608 Metric); PART TYPE: Capacitors; PIN NAMES ROTATE: True; PIN NAMES VISIBLE: False; PIN NUMBERS VISIBLE: False; SAVECOUNT: 0; SIZECODESMD: 1608; TEMPERATURE COEFFICIENT: X7R; TIME: 16:56:59; TOLERANCE: }10%; UPDATEDATE: 2024/2/16; UPDATETIME: 16:56:59; UPDATEUSER: t5459927; VAL1: 0.1uF(K); VAL2: 50V; VAL3: CL10B104KB8NNNC; VOLTAGE RATED: 50V
C59 = C: ASSEMBLY: SMD; AUTHOR: t5459927; BARCODE: 0100000013731; CATEGORY: Capacitors; COMP: Capacitor_Ceramic_C59; COMPONENTNAME: Capacitor_Ceramic_C59_Capacitor_Ceramic_C59; COMPONENTTYPE: 4; DATASHEET URL: http://www.yageo.com/documents/recent/UPY-GP_NP0_16V-to-50V_10.pdf; DATE: 2024/2/16; FAMILY: CERAMIC CAPACITOR; ID: 145; INSTANCENAME: INS4323; ITEM_ID: 1791; LAYOUTNAME: Z-99fa7a59-0340-4c54-926f-366210f15152.cmp57; MANUFACTURER: Yageo; MANUFACTURER PART NUMBER: CC0603JRNPO9BN220; NUMBER DEVICES IN PACKAGE: 1; PACKAGE CASE: 0603 (1608 Metric); PART TYPE: Capacitors; PIN NAMES ROTATE: True; PIN NAMES VISIBLE: False; PIN NUMBERS VISIBLE: False; RECOMMENDED RATING: Platinum; SAVECOUNT: 0; SIZECODESMD: 1608; TEMPERATURE COEFFICIENT: C0G, NP0; TIME: 16:56:45; TOLERANCE: }5%; UPDATEDATE: 2024/2/16; UPDATETIME: 16:56:45; UPDATEUSER: t5459927; VAL1: 22pF(J); VAL2: 50V; VAL3: CC0603JRNPO9BN220; VOLTAGE RATED: 50V
C60 = C: ASSEMBLY: SMD; AUTHOR: t5459927; BARCODE: 0100000012857; CATEGORY: Capacitors; COMP: Capacitor_Ceramic_C60; COMPONENTNAME: Capacitor_Ceramic_C60_Capacitor_Ceramic_C60; COMPONENTTYPE: 4; DATASHEET URL: http://www.samsungsem.com/kr/support/product-search/mlcc/CL10B104KB8NNNC.jsp; DATE: 2024/2/16; FAMILY: CERAMIC CAPACITOR; ID: 275; INSTANCENAME: INS4607; ITEM_ID: 1703; LAYOUTNAME: Z-99fa7a59-0340-4c54-926f-366210f15152.cmp31; MANUFACTURER: Samsung Electro-Mechanics America, Inc.; MANUFACTURER PART NUMBER: CL10B104KB8NNNC; NUMBER DEVICES IN PACKAGE: 1; PACKAGE CASE: 0603 (1608 Metric); PART TYPE: Capacitors; PIN NAMES ROTATE: True; PIN NAMES VISIBLE: False; PIN NUMBERS VISIBLE: False; SAVECOUNT: 0; SIZECODESMD: 1608; TEMPERATURE COEFFICIENT: X7R; TIME: 16:56:37; TOLERANCE: }10%; UPDATEDATE: 2024/2/16; UPDATETIME: 16:56:37; UPDATEUSER: t5459927; VAL1: 0.1uF(K); VAL2: 50V; VAL3: CL10B104KB8NNNC; VOLTAGE RATED: 50V
C61 = C: ASSEMBLY: SMD; AUTHOR: t5459927; BARCODE: 0100000012857; CATEGORY: Capacitors; COMP: Capacitor_Ceramic_C61; COMPONENTNAME: Capacitor_Ceramic_C61_Capacitor_Ceramic_C61; COMPONENTTYPE: 4; DATASHEET URL: http://www.samsungsem.com/kr/support/product-search/mlcc/CL10B104KB8NNNC.jsp; DATE: 2024/2/16; FAMILY: CERAMIC CAPACITOR; ID: 275; INSTANCENAME: INS4617; ITEM_ID: 1703; LAYOUTNAME: Z-99fa7a59-0340-4c54-926f-366210f15152.cmp58; MANUFACTURER: Samsung Electro-Mechanics America, Inc.; MANUFACTURER PART NUMBER: CL10B104KB8NNNC; NUMBER DEVICES IN PACKAGE: 1; PACKAGE CASE: 0603 (1608 Metric); PART TYPE: Capacitors; PIN NAMES ROTATE: True; PIN NAMES VISIBLE: False; PIN NUMBERS VISIBLE: False; SAVECOUNT: 0; SIZECODESMD: 1608; TEMPERATURE COEFFICIENT: X7R; TIME: 16:56:52; TOLERANCE: }10%; UPDATEDATE: 2024/2/16; UPDATETIME: 16:56:52; UPDATEUSER: t5459927; VAL1: 0.1uF(K); VAL2: 50V; VAL3: CL10B104KB8NNNC; VOLTAGE RATED: 50V
FB1 = FL08A: ASSEMBLY: SMD; BARCODE: 3500000320889; CATEGORY: Filters; COMP: FERRITE_FB1; COMPONENTNAME: FERRITE_FB1_FERRITE_FB1; COMPONENTTYPE: 4; CURRENT RATING: 1.7A; DATASHEET URL: https://www.murata.com/en-us/products/productdata/8796733866014/S0594E.pdf; DC RESISTANCE: 80m; FILTER TYPE: Power Line; ID: 427; INSTANCENAME: INS4647; ITEM_ID: 29239; MANUFACTURER: Murata Electronics; MANUFACTURER PART NUMBER: BLM18KG331SZ1D; NUMBER DEVICES IN PACKAGE: 1; PACKAGE CASE: 0603 (1608 Metric); PART TYPE: Inductor, Transf, Filter, Ferrite; PIN NAMES ROTATE: True; PIN NAMES VISIBLE: False; PIN NUMBERS VISIBLE: False; SIZECODESMD: 1608; VAL3: BLM18KG331SZ1D
J33 = HM_1X2_J18: COMPONENTTYPE: 4; LAYOUTNAME: Z-99fa7a59-0340-4c54-926f-366210f15152.cmp99; VAL3: 61300211121
LD5 = LED: ASSEMBLY: SMD; BARCODE: 2911010024321; COMP: LED_RED_LD5; COMPONENTNAME: LED_RED_LD5_LED_RED_LD5; COMPONENTTYPE: 4; ID: 35; INSTANCENAME: INS4719; ITEM_ID: 3341; LAYOUTNAME: Z-99fa7a59-0340-4c54-926f-366210f15152.cmp53; MANUFACTURER: BRIGHT LED ELECTRONICS; MANUFACTURER PART NUMBER: BL-HUB35A-AV-TRB; NUMBER DEVICES IN PACKAGE: 1; PACKAGE CASE: 0805 (2012 Metric); PART TYPE: Optoelectronics; PIN NAMES ROTATE: True; PIN NAMES VISIBLE: False; PIN NUMBERS VISIBLE: False; RECOMMENDED RATING: Platinum; SIZECODESMD: 2012; VAL1: RED; VAL3: BL-HUB35A-AV-TRB; VOLTAGE FORWARD: 2.0 V
Q8 = PJC7401: ASSEMBLY: SMD; BARCODE: 3500000281548; COMP: MOSFET_P_CH_Q8; COMPONENTNAME: MOSFET_P_CH_Q8_MOSFET_P_CH_Q8; COMPONENTTYPE: 4; CURRENT  CONTINUOUS DRAIN: 1.5A; DATASHEET URL: https://www.panjit.com.tw/upload/datasheet/PJC7401.pdf; DRAIN TO SOURCE VOLTAGE: 30V; FAMILY: FET; FET TYPE: MOSFET P-Channel, Metal Oxide; ID: 656; INSTANCENAME: INS4707; ITEM_ID: 25299; LAYOUTNAME: Z-99fa7a59-0340-4c54-926f-366210f15152.cmp38; MANUFACTURER: PANJIT; NUMBER DEVICES IN PACKAGE: 1; PACKAGE CASE: SC-70, SOT-323; PART TYPE: Discrete Semiconductors; PIN NAMES ROTATE: True; PIN NAMES VISIBLE: False; PIN NUMBERS VISIBLE: True; POWER MAX: 350mW; RDS ON MAX: 115 Ohm
R44 = R: ASSEMBLY: SMD; AUTHOR: t5459927; BARCODE: 3500000287397; CATEGORY: Resistors; COMP: Resistor_R44; COMPONENTNAME: Resistor_R44_Resistor_R44; COMPONENTTYPE: 4; DATASHEET URL: https://www.yageo.com/upload/media/product/productsearch/datasheet/rchip/PYu-RC_Group_51_RoHS_L_11.pdf; DATE: 2024/2/16; FAMILY: RESISTOR; ID: 1525; INSTANCENAME: INS4215; ITEM_ID: 25884; LAYOUTNAME: Z-99fa7a59-0340-4c54-926f-366210f15152.cmp4; MANUFACTURER: Yageo; MANUFACTURER PART NUMBER: RC0603FR-072R2L; NUMBER DEVICES IN PACKAGE: 1; PACKAGE CASE: 0603 (1608 Metric); PART TYPE: Resistors; PIN NAMES ROTATE: True; PIN NAMES VISIBLE: False; PIN NUMBERS VISIBLE: False; POWER: 0.1W, 1/10W; SAVECOUNT: 0; SIZECODESMD: 1608; TEMPERATURE COEFFICIENT: }200ppm/C; TIME: 16:57:00; TOLERANCE: }1%; UPDATEDATE: 2024/2/16; UPDATETIME: 16:57:00; UPDATEUSER: t5459927; VAL1: 2.2(F); VAL2: 0.1W; VAL3: RC0603FR-072R2L
R45 = R: ASSEMBLY: SMD; AUTHOR: t5459927; BARCODE: 0100000013458; CATEGORY: Resistors; COMP: Resistor_R45; COMPONENTNAME: Resistor_R45_Resistor_R45; COMPONENTTYPE: 4; DATASHEET URL: http://www.yageo.com/NewPortal/yageodocoutput?fileName; DATE: 2024/2/16; FAMILY: RESISTOR; ID: 111; INSTANCENAME: INS4205; ITEM_ID: 1763; LAYOUTNAME: Z-99fa7a59-0340-4c54-926f-366210f15152.cmp16; MANUFACTURER: Yageo; MANUFACTURER PART NUMBER: RC0603FR-07220RL; NUMBER DEVICES IN PACKAGE: 1; PACKAGE CASE: 0603 (1608 Metric); PART TYPE: Resistors; PIN NAMES ROTATE: True; PIN NAMES VISIBLE: False; PIN NUMBERS VISIBLE: False; POWER: 0.1W, 1/10W; RECOMMENDED RATING: Gold; SAVECOUNT: 0; SIZECODESMD: 1608; TEMPERATURE COEFFICIENT: }100ppm/C; TIME: 16:56:46; TOLERANCE: }1%; UPDATEDATE: 2024/2/16; UPDATETIME: 16:56:46; UPDATEUSER: t5459927; VAL1: 220(F); VAL2: 0.1W; VAL3: RC0603FR-07220RL
R46 = R: ASSEMBLY: SMD; AUTHOR: t5459927; BARCODE: 0100000074183; CATEGORY: Resistors; COMP: Resistor_R46; COMPONENTNAME: Resistor_R46_Resistor_R46; COMPONENTTYPE: 4; DATASHEET URL: https://www.yageo.com/upload/media/product/productsearch/datasheet/rchip/PYu-RC_Group_51_RoHS_L_11.pdf; DATE: 2024/2/16; FAMILY: RESISTOR; ID: 1524; INSTANCENAME: INS4175; ITEM_ID: 6563; LAYOUTNAME: Z-99fa7a59-0340-4c54-926f-366210f15152.cmp17; MANUFACTURER: Yageo; MANUFACTURER PART NUMBER: RC0603JR-070RL; NUMBER DEVICES IN PACKAGE: 1; PACKAGE CASE: 0603 (1608 Metric); PART TYPE: Resistors; PIN NAMES ROTATE: True; PIN NAMES VISIBLE: False; PIN NUMBERS VISIBLE: False; POWER: 0.1W, 1/10W; SAVECOUNT: 0; SIZECODESMD: 1608; TIME: 16:56:51; TOLERANCE: Jumper; UPDATEDATE: 2024/2/16; UPDATETIME: 16:56:51; UPDATEUSER: t5459927; VAL1: 0; VAL2: 0.1W; VAL3: RC0603JR-070RL
R47 = R: ASSEMBLY: SMD; AUTHOR: t5459927; BARCODE: 0100000013403; CATEGORY: Resistors; COMP: Resistor_R47; COMPONENTNAME: Resistor_R47_Resistor_R47; COMPONENTTYPE: 4; DATASHEET URL: http://www.yageo.com/NewPortal/yageodocoutput?fileName; DATE: 2024/2/16; FAMILY: RESISTOR; ID: 113; INSTANCENAME: INS4185; ITEM_ID: 1758; LAYOUTNAME: Z-99fa7a59-0340-4c54-926f-366210f15152.cmp32; MANUFACTURER: Yageo; MANUFACTURER PART NUMBER: RC0603FR-07100RL; NUMBER DEVICES IN PACKAGE: 1; PACKAGE CASE: 0603 (1608 Metric); PART TYPE: Resistors; PIN NAMES ROTATE: True; PIN NAMES VISIBLE: False; PIN NUMBERS VISIBLE: False; POWER: 0.1W, 1/10W; RECOMMENDED RATING: Gold; SAVECOUNT: 0; SIZECODESMD: 1608; TEMPERATURE COEFFICIENT: }100ppm/C; TIME: 16:56:41; TOLERANCE: }1%; UPDATEDATE: 2024/2/16; UPDATETIME: 16:56:41; UPDATEUSER: t5459927; VAL1: 100(F); VAL2: 0.1W; VAL3: RC0603FR-07100RL
R48 = R: ASSEMBLY: SMD; AUTHOR: t5459927; BARCODE: 3500000287397; CATEGORY: Resistors; COMP: Resistor_R48; COMPONENTNAME: Resistor_R48_Resistor_R48; COMPONENTTYPE: 4; DATASHEET URL: https://www.yageo.com/upload/media/product/productsearch/datasheet/rchip/PYu-RC_Group_51_RoHS_L_11.pdf; DATE: 2024/2/16; FAMILY: RESISTOR; ID: 1525; INSTANCENAME: INS4225; ITEM_ID: 25884; LAYOUTNAME: Z-99fa7a59-0340-4c54-926f-366210f15152.cmp18; MANUFACTURER: Yageo; MANUFACTURER PART NUMBER: RC0603FR-072R2L; NUMBER DEVICES IN PACKAGE: 1; PACKAGE CASE: 0603 (1608 Metric); PART TYPE: Resistors; PIN NAMES ROTATE: True; PIN NAMES VISIBLE: False; PIN NUMBERS VISIBLE: False; POWER: 0.1W, 1/10W; SAVECOUNT: 0; SIZECODESMD: 1608; TEMPERATURE COEFFICIENT: }200ppm/C; TIME: 16:56:50; TOLERANCE: }1%; UPDATEDATE: 2024/2/16; UPDATETIME: 16:56:50; UPDATEUSER: t5459927; VAL1: 2.2(F); VAL2: 0.1W; VAL3: RC0603FR-072R2L
R49 = R: ASSEMBLY: SMD; AUTHOR: t5459927; BARCODE: 0100000013458; CATEGORY: Resistors; COMP: Resistor_R49; COMPONENTNAME: Resistor_R49_Resistor_R49; COMPONENTTYPE: 4; DATASHEET URL: http://www.yageo.com/NewPortal/yageodocoutput?fileName; DATE: 2024/2/16; FAMILY: RESISTOR; ID: 111; INSTANCENAME: INS4195; ITEM_ID: 1763; LAYOUTNAME: Z-99fa7a59-0340-4c54-926f-366210f15152.cmp20; MANUFACTURER: Yageo; MANUFACTURER PART NUMBER: RC0603FR-07220RL; NUMBER DEVICES IN PACKAGE: 1; PACKAGE CASE: 0603 (1608 Metric); PART TYPE: Resistors; PIN NAMES ROTATE: True; PIN NAMES VISIBLE: False; PIN NUMBERS VISIBLE: False; POWER: 0.1W, 1/10W; RECOMMENDED RATING: Gold; SAVECOUNT: 0; SIZECODESMD: 1608; TEMPERATURE COEFFICIENT: }100ppm/C; TIME: 16:56:55; TOLERANCE: }1%; UPDATEDATE: 2024/2/16; UPDATETIME: 16:56:56; UPDATEUSER: t5459927; VAL1: 220(F); VAL2: 0.1W; VAL3: RC0603FR-07220RL
R50 = R: ASSEMBLY: SMD; AUTHOR: t5459927; BARCODE: 2911010021887; CATEGORY: Resistors; COMP: Resistor_R50; COMPONENTNAME: Resistor_R50_Resistor_R50; COMPONENTTYPE: 4; DATASHEET URL: http://www.yageo.com/NewPortal/yageodocoutput?fileName; DATE: 2024/2/16; FAMILY: RESISTOR; ID: 104; INSTANCENAME: INS4353; ITEM_ID: 3097; LAYOUTNAME: Z-99fa7a59-0340-4c54-926f-366210f15152.cmp10; MANUFACTURER: Yageo; MANUFACTURER PART NUMBER: RC0603FR-074K7L; NUMBER DEVICES IN PACKAGE: 1; PACKAGE CASE: 0603 (1608 Metric); PART TYPE: Resistors; PIN NAMES ROTATE: True; PIN NAMES VISIBLE: False; PIN NUMBERS VISIBLE: False; POWER: 0.1W, 1/10W; RECOMMENDED RATING: Gold; SAVECOUNT: 0; SIZECODESMD: 1608; TEMPERATURE COEFFICIENT: }100ppm/C; TIME: 16:56:37; TOLERANCE: }1%; UPDATEDATE: 2024/2/16; UPDATETIME: 16:56:37; UPDATEUSER: t5459927; VAL1: 4.7k(F); VAL2: 0.1W; VAL3: RC0603FR-074K7L
R51 = R: ASSEMBLY: SMD; AUTHOR: t5459927; BARCODE: 0100000109397; CATEGORY: Resistors; COMP: Resistor_R51; COMPONENTNAME: Resistor_R51_Resistor_R51; COMPONENTTYPE: 4; DATASHEET URL: http://www.yageo.com/documents/recent/PYu-RT_1-to-0.05_RoHS_L_6.pdf; DATE: 2024/2/16; FAMILY: RESISTOR; ID: 395; INSTANCENAME: INS4275; ITEM_ID: 10053; LAYOUTNAME: Z-99fa7a59-0340-4c54-926f-366210f15152.cmp25; MANUFACTURER: Yageo; MANUFACTURER PART NUMBER: RT0603BRD079K1L; NUMBER DEVICES IN PACKAGE: 1; PACKAGE CASE: 0603 (1608 Metric); PART TYPE: Resistors; PIN NAMES ROTATE: True; PIN NAMES VISIBLE: False; PIN NUMBERS VISIBLE: False; POWER: 0.1W, 1/10W; SAVECOUNT: 0; SIZECODESMD: 1608; TEMPERATURE COEFFICIENT: }25ppm/C; TIME: 16:56:48; TOLERANCE: }0.1%; UPDATEDATE: 2024/2/16; UPDATETIME: 16:56:49; UPDATEUSER: t5459927; VAL1: 9.1K(B); VAL2: 0.1W; VAL3: RT0603BRD079K1L
R52 = R: ASSEMBLY: SMD; AUTHOR: t5459927; BARCODE: 0100000013427; CATEGORY: Resistors; COMP: Resistor_R52; COMPONENTNAME: Resistor_R52_Resistor_R52; COMPONENTTYPE: 4; DATASHEET URL: http://www.yageo.com/NewPortal/yageodocoutput?fileName; DATE: 2024/2/16; FAMILY: RESISTOR; ID: 193; INSTANCENAME: INS4687; ITEM_ID: 1760; LAYOUTNAME: Z-99fa7a59-0340-4c54-926f-366210f15152.cmp50; MANUFACTURER: Yageo; MANUFACTURER PART NUMBER: RC0603FR-0710KL; NUMBER DEVICES IN PACKAGE: 1; PACKAGE CASE: 0603 (1608 Metric); PART TYPE: Resistors; PIN NAMES ROTATE: True; PIN NAMES VISIBLE: False; PIN NUMBERS VISIBLE: False; POWER: 0.1W, 1/10W; SAVECOUNT: 0; SIZECODESMD: 1608; TEMPERATURE COEFFICIENT: }100ppm/C; TIME: 16:56:54; TOLERANCE: }1%; UPDATEDATE: 2024/2/16; UPDATETIME: 16:56:54; UPDATEUSER: t5459927; VAL1: 10k(F); VAL2: 0.1W; VAL3: RC0603FR-0710KL
R53 = R: ASSEMBLY: SMD; AUTHOR: t5459927; BARCODE: 0100000003947; CATEGORY: Resistors; COMP: Resistor_R53; COMPONENTNAME: Resistor_R53_Resistor_R53; COMPONENTTYPE: 4; DATASHEET URL: http://www.yageo.com/NewPortal/yageodocoutput?fileName; DATE: 2024/2/16; FAMILY: RESISTOR; ID: 233; INSTANCENAME: INS4729; ITEM_ID: 660; LAYOUTNAME: Z-99fa7a59-0340-4c54-926f-366210f15152.cmp9; MANUFACTURER: Yageo; MANUFACTURER PART NUMBER: RC0805JR-070RL; NUMBER DEVICES IN PACKAGE: 1; PACKAGE CASE: 0805 (2012 Metric); PART TYPE: Resistors; PIN NAMES ROTATE: True; PIN NAMES VISIBLE: False; PIN NUMBERS VISIBLE: False; POWER: 0.125W, 1/8W; SAVECOUNT: 0; SIZECODESMD: 2012; TIME: 16:56:42; TOLERANCE: Jumper; UPDATEDATE: 2024/2/16; UPDATETIME: 16:56:42; UPDATEUSER: t5459927; VAL1: 0; VAL2: 0.125W; VAL3: RC0805JR-070RL
R54 = R: ASSEMBLY: SMD; AUTHOR: t5459927; BARCODE: 0100000109397; CATEGORY: Resistors; COMP: Resistor_R54; COMPONENTNAME: Resistor_R54_Resistor_R54; COMPONENTTYPE: 4; DATASHEET URL: http://www.yageo.com/documents/recent/PYu-RT_1-to-0.05_RoHS_L_6.pdf; DATE: 2024/2/16; FAMILY: RESISTOR; ID: 395; INSTANCENAME: INS4235; ITEM_ID: 10053; LAYOUTNAME: Z-99fa7a59-0340-4c54-926f-366210f15152.cmp39; MANUFACTURER: Yageo; MANUFACTURER PART NUMBER: RT0603BRD079K1L; NUMBER DEVICES IN PACKAGE: 1; PACKAGE CASE: 0603 (1608 Metric); PART TYPE: Resistors; PIN NAMES ROTATE: True; PIN NAMES VISIBLE: False; PIN NUMBERS VISIBLE: False; POWER: 0.1W, 1/10W; SAVECOUNT: 0; SIZECODESMD: 1608; TEMPERATURE COEFFICIENT: }25ppm/C; TIME: 16:56:41; TOLERANCE: }0.1%; UPDATEDATE: 2024/2/16; UPDATETIME: 16:56:41; UPDATEUSER: t5459927; VAL1: 9.1K(B); VAL2: 0.1W; VAL3: RT0603BRD079K1L
R55 = R: ASSEMBLY: SMD; AUTHOR: t5459927; BARCODE: 2911010042394; CATEGORY: Resistors; COMP: Resistor_R55; COMPONENTNAME: Resistor_R55_Resistor_R55; COMPONENTTYPE: 4; DATASHEET URL: http://www.yageo.com/NewPortal/yageodocoutput?fileName; DATE: 2024/2/16; FAMILY: RESISTOR; ID: 44; INSTANCENAME: INS4697; ITEM_ID: 4919; LAYOUTNAME: Z-99fa7a59-0340-4c54-926f-366210f15152.cmp14; MANUFACTURER: Yageo; MANUFACTURER PART NUMBER: RC0402FR-074K7L; NUMBER DEVICES IN PACKAGE: 1; PACKAGE CASE: 0402 (1005 Metric); PART TYPE: Resistors; PIN NAMES ROTATE: True; PIN NAMES VISIBLE: False; PIN NUMBERS VISIBLE: False; POWER: 0.063W, 1/16W; RECOMMENDED RATING: Gold; SAVECOUNT: 0; SIZECODESMD: 1005; TEMPERATURE COEFFICIENT: }100ppm/C; TIME: 16:56:45; TOLERANCE: }1%; UPDATEDATE: 2024/2/16; UPDATETIME: 16:56:45; UPDATEUSER: t5459927; VAL1: 4.7k(F); VAL2: 63mW; VAL3: RC0402FR-074K7L
R56 = R: ASSEMBLY: SMD; AUTHOR: t5459927; BARCODE: 2911010021887; CATEGORY: Resistors; COMP: Resistor_R56; COMPONENTNAME: Resistor_R56_Resistor_R56; COMPONENTTYPE: 4; DATASHEET URL: http://www.yageo.com/NewPortal/yageodocoutput?fileName; DATE: 2024/2/16; FAMILY: RESISTOR; ID: 104; INSTANCENAME: INS4627; ITEM_ID: 3097; LAYOUTNAME: Z-99fa7a59-0340-4c54-926f-366210f15152.cmp52; MANUFACTURER: Yageo; MANUFACTURER PART NUMBER: RC0603FR-074K7L; NUMBER DEVICES IN PACKAGE: 1; PACKAGE CASE: 0603 (1608 Metric); PART TYPE: Resistors; PIN NAMES ROTATE: True; PIN NAMES VISIBLE: False; PIN NUMBERS VISIBLE: False; POWER: 0.1W, 1/10W; RECOMMENDED RATING: Gold; SAVECOUNT: 0; SIZECODESMD: 1608; TEMPERATURE COEFFICIENT: }100ppm/C; TIME: 16:56:42; TOLERANCE: }1%; UPDATEDATE: 2024/2/16; UPDATETIME: 16:56:42; UPDATEUSER: t5459927; VAL1: 4.7k(F); VAL2: 0.1W; VAL3: RC0603FR-074K7L
R57 = R: ASSEMBLY: SMD; AUTHOR: t5459927; BARCODE: 0100000012888; CATEGORY: Resistors; COMP: Resistor_R57; COMPONENTNAME: Resistor_R57_Resistor_R57; COMPONENTTYPE: 4; DATASHEET URL: http://www.yageo.com/NewPortal/yageodocoutput?fileName; DATE: 2024/2/16; FAMILY: RESISTOR; ID: 196; INSTANCENAME: INS4363; ITEM_ID: 1706; LAYOUTNAME: Z-99fa7a59-0340-4c54-926f-366210f15152.cmp42; MANUFACTURER: Yageo; MANUFACTURER PART NUMBER: RC0603FR-071KL; NUMBER DEVICES IN PACKAGE: 1; PACKAGE CASE: 0603 (1608 Metric); PART TYPE: Resistors; PIN NAMES ROTATE: True; PIN NAMES VISIBLE: False; PIN NUMBERS VISIBLE: False; POWER: 0.1W, 1/10W; RECOMMENDED RATING: Platinum; SAVECOUNT: 0; SIZECODESMD: 1608; TEMPERATURE COEFFICIENT: }100ppm/C; TIME: 16:56:52; TOLERANCE: }1%; UPDATEDATE: 2024/2/16; UPDATETIME: 16:56:53; UPDATEUSER: t5459927; VAL1: 1K(F); VAL2: 0.1W; VAL3: RC0603FR-071KL
R58 = R: ASSEMBLY: SMD; AUTHOR: t5459927; BARCODE: 2911010021887; CATEGORY: Resistors; COMP: Resistor_R58; COMPONENTNAME: Resistor_R58_Resistor_R58; COMPONENTTYPE: 4; DATASHEET URL: http://www.yageo.com/NewPortal/yageodocoutput?fileName; DATE: 2024/2/16; FAMILY: RESISTOR; ID: 104; INSTANCENAME: INS4637; ITEM_ID: 3097; LAYOUTNAME: Z-99fa7a59-0340-4c54-926f-366210f15152.cmp51; MANUFACTURER: Yageo; MANUFACTURER PART NUMBER: RC0603FR-074K7L; NUMBER DEVICES IN PACKAGE: 1; PACKAGE CASE: 0603 (1608 Metric); PART TYPE: Resistors; PIN NAMES ROTATE: True; PIN NAMES VISIBLE: False; PIN NUMBERS VISIBLE: False; POWER: 0.1W, 1/10W; RECOMMENDED RATING: Gold; SAVECOUNT: 0; SIZECODESMD: 1608; TEMPERATURE COEFFICIENT: }100ppm/C; TIME: 16:56:56; TOLERANCE: }1%; UPDATEDATE: 2024/2/16; UPDATETIME: 16:56:56; UPDATEUSER: t5459927; VAL1: 4.7k(F); VAL2: 0.1W; VAL3: RC0603FR-074K7L
R59 = R: ASSEMBLY: SMD; AUTHOR: t5459927; BARCODE: 2911010025670; CATEGORY: Resistors; COMP: Resistor_R59; COMPONENTNAME: Resistor_R59_Resistor_R59; COMPONENTTYPE: 4; DATASHEET URL: http://www.yageo.com/NewPortal/yageodocoutput?fileName; DATE: 2024/2/16; FAMILY: RESISTOR; ID: 99; INSTANCENAME: INS4373; ITEM_ID: 3476; LAYOUTNAME: Z-99fa7a59-0340-4c54-926f-366210f15152.cmp7; MANUFACTURER: Yageo; MANUFACTURER PART NUMBER: RC0603FR-0722KL; NUMBER DEVICES IN PACKAGE: 1; PACKAGE CASE: 0603 (1608 Metric); PART TYPE: Resistors; PIN NAMES ROTATE: True; PIN NAMES VISIBLE: False; PIN NUMBERS VISIBLE: False; POWER: 0.1W, 1/10W; RECOMMENDED RATING: Silver; SAVECOUNT: 0; SIZECODESMD: 1608; TEMPERATURE COEFFICIENT: }100ppm/C; TIME: 16:56:43; TOLERANCE: }1%; UPDATEDATE: 2024/2/16; UPDATETIME: 16:56:43; UPDATEUSER: t5459927; VAL1: 22k(F); VAL2: 0.1W; VAL3: RC0603FR-0722KL
R60 = R: ASSEMBLY: SMD; AUTHOR: t5459927; BARCODE: 0100000012888; CATEGORY: Resistors; COMP: Resistor_R60; COMPONENTNAME: Resistor_R60_Resistor_R60; COMPONENTTYPE: 4; DATASHEET URL: http://www.yageo.com/NewPortal/yageodocoutput?fileName; DATE: 2024/2/16; FAMILY: RESISTOR; ID: 196; INSTANCENAME: INS4383; ITEM_ID: 1706; LAYOUTNAME: Z-99fa7a59-0340-4c54-926f-366210f15152.cmp46; MANUFACTURER: Yageo; MANUFACTURER PART NUMBER: RC0603FR-071KL; NUMBER DEVICES IN PACKAGE: 1; PACKAGE CASE: 0603 (1608 Metric); PART TYPE: Resistors; PIN NAMES ROTATE: True; PIN NAMES VISIBLE: False; PIN NUMBERS VISIBLE: False; POWER: 0.1W, 1/10W; RECOMMENDED RATING: Platinum; SAVECOUNT: 0; SIZECODESMD: 1608; TEMPERATURE COEFFICIENT: }100ppm/C; TIME: 16:56:57; TOLERANCE: }1%; UPDATEDATE: 2024/2/16; UPDATETIME: 16:56:57; UPDATEUSER: t5459927; VAL1: 1k(F); VAL2: 0.1W; VAL3: RC0603FR-071KL
U5 = TC75W58FU_1: ASSEMBLY: SMD; BARCODE: 3500000317650; CATEGORY: Integrated Circuits (ICs); COMP: MCP6282T_E_MS_U5A; COMPONENTNAME: MCP6282T_E_MS_U5A_2; COMPONENTTYPE: 8; CaptureCellPackProp: TC75W58FU_1B; DATASHEET URL: https://toshiba.semicon-storage.com/info/docget.jsp?did; FAMILY: Linear Amplifiers; FUNCN: MCP6282T_E_MS_U5A_2; ID: 3601; INSTANCENAME: INS4301; ITEM_ID: 28913; LAYOUTNAME: Z-99fa7a59-0340-4c54-926f-366210f15152.cmp27; MANUFACTURER: Toshiba Semiconductor and Storage; MANUFACTURER PART NUMBER: TC75W58FU; NUMBER DEVICES IN PACKAGE: 1; OUTPUT TYPE: Open Drain; PACKAGE CASE: 8-TSSOP, 8-MSOP (0.110", 2.80mm Width); PACKAGEHETEROGENEOUS: MCP6282T-E/MS_U5; PART TYPE: Integrated Circuits; PIN NAMES ROTATE: True; PIN NAMES VISIBLE: False; PIN NUMBERS VISIBLE: True; USERCOMPTEXT3: TOSHIBA; VAL1: TC75W58FU; VAL3: TC75W58FU; VOLTAGE SUPPLY SINGLE DUAL: 1.8V ~ 7V, }0.9V ~ 3.5V
U6 = OPA365AID: AMPLIFIER TYPE: General Purpose; ASSEMBLY: SMD; BARCODE: 3500000317667; CATEGORY: Integrated Circuits (ICs); COMP: OPA365AID_U6; COMPONENTNAME: OPA365AID_U6_OPA365AID_U6; COMPONENTTYPE: 4; CURRENT  SUPPLY: 4.6mA; CURRENT OUTPUT: 65mA; DATASHEET URL: https://www.ti.com/general/docs/suppproductinfo.tsp?distId; FAMILY: Linear Amplifiers; GAIN BANDWIDTH PRODUCT: 50MHz; ID: 3602; INSTANCENAME: INS4143; ITEM_ID: 28914; LAYOUTNAME: Z-99fa7a59-0340-4c54-926f-366210f15152.cmp47; MANUFACTURER: Texas Instruments; NUMBER DEVICES IN PACKAGE: 1; OUTPUT TYPE: Rail-to-Rail; PACKAGE CASE: 8-SOIC (0.154", 3.90mm Width); PART TYPE: Integrated Circuits; PIN NAMES ROTATE: True; PIN NAMES VISIBLE: True; PIN NUMBERS VISIBLE: True; VOLTAGE SUPPLY SINGLE DUAL: 2.2V ~ 5.5V, }1.1V ~ 2.25V
U7 = LM321: AMPLIFIER TYPE: General Purpose; ASSEMBLY: SMD; AUTHOR: t5459927; BARCODE: 3500000317674; CATEGORY: Integrated Circuits (ICs); COMP: LM321MFX_NOPB_U7; COMPONENTNAME: LM321MFX_NOPB_U7_LM321MFX_NOPB_U7; COMPONENTTYPE: 4; CURRENT  SUPPLY: 660ƒÊA; CURRENT OUTPUT: 40mA; DATASHEET URL: https://www.ti.com/general/docs/suppproductinfo.tsp?distId; DATE: 2024/2/16; FAMILY: Linear Amplifiers; GAIN BANDWIDTH PRODUCT: 1MHz; ID: 3603; INSTANCENAME: INS4591; ITEM_ID: 28915; LAYOUTNAME: Z-99fa7a59-0340-4c54-926f-366210f15152.cmp26; MANUFACTURER: Texas Instruments; MANUFACTURER PART NUMBER: LM321MFX/NOPB; NUMBER DEVICES IN PACKAGE: 1; PACKAGE CASE: SC-74A, SOT-753; PART TYPE: Integrated Circuits; PIN NAMES ROTATE: True; PIN NAMES VISIBLE: False; PIN NUMBERS VISIBLE: True; SAVECOUNT: 0; TIME: 16:56:38; UPDATEDATE: 2024/2/16; UPDATETIME: 16:56:38; UPDATEUSER: t5459927; VAL1: LM321MFX/NOPB; VAL3: LM321MFX/NOPB; VOLTAGE SUPPLY SINGLE DUAL: 3V ~ 30V, }1.5V ~ 15V
U?#2 = WAKU_DEF100: AUTHOR: w20165dm; COMPONENTTYPE: 2; DATE: 2024/03/12; DRAWINGNUMBER: RD228-SCHEMATIC-01; FUNCTION: Over current detection; LAYOUTNAME: Z-99fa7a59-0340-4c54-926f-366210f15152.cmp63; REVISION: 01; SAVEAREA0: 185750,-43960,448537,75779; SAVECOUNT: 9; SHEETNUMBER: 5/7; SHTSAVECOUNT: 50; TIME: 13:12:21; TITLE: Motor Driving Circuit for Automotive / Body Using SmartMCD (TM); UPDATEDATE: 2024/03/18; UPDATETIME: 15:40:29

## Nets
GND: C11.1 C12.1 C13.1 C18.1 C18.2 C19.2 C20.2 C29.1 C29.2 C30.1 C30.2 C32.2 C34.2 C35.2 C36.2 C37.2 C38.2 C52.1 C53.1 C55.1 C57.1 C58.1 C59.1 C60.1 C61.1 CN2.1 CN2.2 CN2.3 CN2.4 CN2.A1B12 CN2.B1A12 CN3.1 CN3.2 CN3.3 CN3.4 CN3.A1B12 CN3.B1A12 FB1.1 J2.6 J3.5 Q1.2(Source) Q8.2 R5.1 R11.2 R12.2 R17.1 R18.1 R35.1 R36.1 R52.2 R55.2 R58.1 R60.1 R61.1 R62.1 SW1.1 TVS1.1 TVS1.4 TVS2.1 TVS2.4 U2.2 U2.3 U2.24 U2.41 U2.47 U2.49 U4.9 U4.15 U5.4 U6.4 U7.2 U9.4 U9.7 U9.18 U9.20 U9.21 U9.25 U9.26 ; also on sheet 1 2 6 7
VCC-3.3V: C19.1 C34.1 C35.1 C36.1 C37.1 C38.1 J3.1 M1.2 R1.1 R7.1 R8.2 R15.2 R16.2 R22.1 R25.1 U2.4 U2.23 U2.34 U2.44 U2.45 U4.2 ; also on sheet 1
VCC-USB: R86.1 U2.13
VDDA: C52.2 C53.2 C60.2 FB1.2 R56.2 R57.2 U5.8 U6.7 U7.5
ADIN: C55.2 J33.1 R47.2
BOOT: J2.2 R7.2 U2.37
CC1_1: CN3.CC1 R62.2
CC1_2: CN2.CC1 R36.2
CC2_1: CN3.CC2 R61.2
COM_IND: LD4.1(C) U2.17
CURR_OFFSET_2V5: R51.1 U7.3 U7.4
EXT-PRG-EN: R16.1 SW1.2 U4.8
I_LIMIT_H: C57.2 R57.1 R59.2 U5.3
I_LIMIT_L: C58.2 R59.1 R60.2 U5.6
I_MEAS: R46.2 R47.1 R50.1
IO0: J14.2(11) ; also on sheet 6 7
IO1: J15.2(11) ; also on sheet 6 7
IO3: J14.4(13) ; also on sheet 6 7
IO4: J15.4(13) ; also on sheet 6 7
IO7: J14.6(15) J33.2(11) ; also on sheet 6 7
IO8: J15.6(15) ; also on sheet 6 7
IO10: J14.8(17) ; also on sheet 6 7
IO11: J15.8(17) ; also on sheet 6 7
OC_OUT: R53.1 U5.1 U5.7
P_USB-D_N: R34.2 TVS1.5 U2.42
P_USB-D_P: R4.1 R33.2 TVS1.2 U2.43
P_USB-N: CN2.DN1 CN2.DN2 R34.1
P_USB_P: CN2.CP1 CN2.DP2 R33.1
P_X1: C13.2 U2.46 Y2.1(OSC1)
P_X2: C12.2 U2.48 Y2.2(OSC2)
PROG_RXD: J2.3 U2.32
PROG_TXD: J2.1 U2.33
PUCTRL: Q1.1(Gate) R5.2 U2.5
REGOUT: C11.2 U2.40
RESET#: U4.10 ; also on sheet 7
RESET_OB#: C20.1 J2.4 J3.3 R8.1 U2.1
RSH: R44.1 ; also on sheet 2 7
RSL: R48.1 ; also on sheet 2 7
RST#: R14.1 R17.2 U9.19
RUN_IND: LD2.1(C) U2.18
RX-LED: LD6.1(C) U9.23
SIG21: C32.1 U9.17
SIG22: LD6.2(A) R11.1
SIG23: LD7.2(A) R12.1
SIG25: LD2.2(A) R22.2
SIG26: LD4.2(A) R25.2
SIG27: J2.5 R18.2 U2.29
SIG28: M1.3 R4.2
SIG29: M1.1 Q1.3(Drain) R1.2
SIG30: CN2.A4B9 CN2.B4A9 R86.2
SIG31: C54.2 R44.2 R45.1
SIG32: C54.1 R48.2 R49.1
SIG33: C56.2 R45.2 R54.1 U6.2
SIG34: C61.2 R56.1 R58.2 U7.1
SIG35: LD5.1(C) R55.1
SIG36: Q8.1 R52.1 R53.2
SIG37: C56.1 R46.1 R54.2 U6.6
SIG38: C59.2 R50.2 U5.2 U5.5
SIG39: LD5.2(A) Q8.3
SIG40: R49.2 R51.2 U6.3
SIG90: CN2.CC2 R35.2
SWCLK: U4.13 ; also on sheet 7
SWCLK_OB: J3.4 U2.38
SWDIO: U4.14 ; also on sheet 7
SWDIO_OB: J3.2 U2.39
T_RESET#: R15.1 U2.27 U4.7
T_SWCLK: U2.25 U4.4
T_SWDIO: U2.26 U4.3
TX-LED: LD7.1(C) U9.22
UART-RX: J14.1 J14.3(12) J14.5(14) J14.7(16) U9.1
UART-TX: J15.1 J15.3(12) J15.5(14) J15.7(16) U9.5
USB-D_N: R20.2 TVS2.5 U9.16
USB-D_P: R19.2 TVS2.2 U9.15
USB_N: CN3.DN1 CN3.DN2 R20.1
USB_P: CN3.CP1 CN3.DP2 R19.1
V-USB: CN3.A4B9 CN3.B4A9 R14.2

Not connected (* = marked no-connect by the designer): CN2 5 6 SBU1 SBU2; CN3 5 6 SBU1 SBU2; J3 6 7 8 9; SW1 3; TVS1 3 6; TVS2 3 6; U2 6 7 8 9 10 11 12 14 15 16 19 20 21 22 28 30 31 35 36; U4 1 5 6 11 12 16; U6 1 5 8; U9 2 3 6 8 9 10 11 12 13 14 24 27 28

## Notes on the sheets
sheet 4
- INT
- EXT
- X5
